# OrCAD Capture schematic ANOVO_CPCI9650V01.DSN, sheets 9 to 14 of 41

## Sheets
9 -GMCH DMI & STRAP (3 of 7): size C; title: 09--GMCH DMI & STRAP (3 of 7)
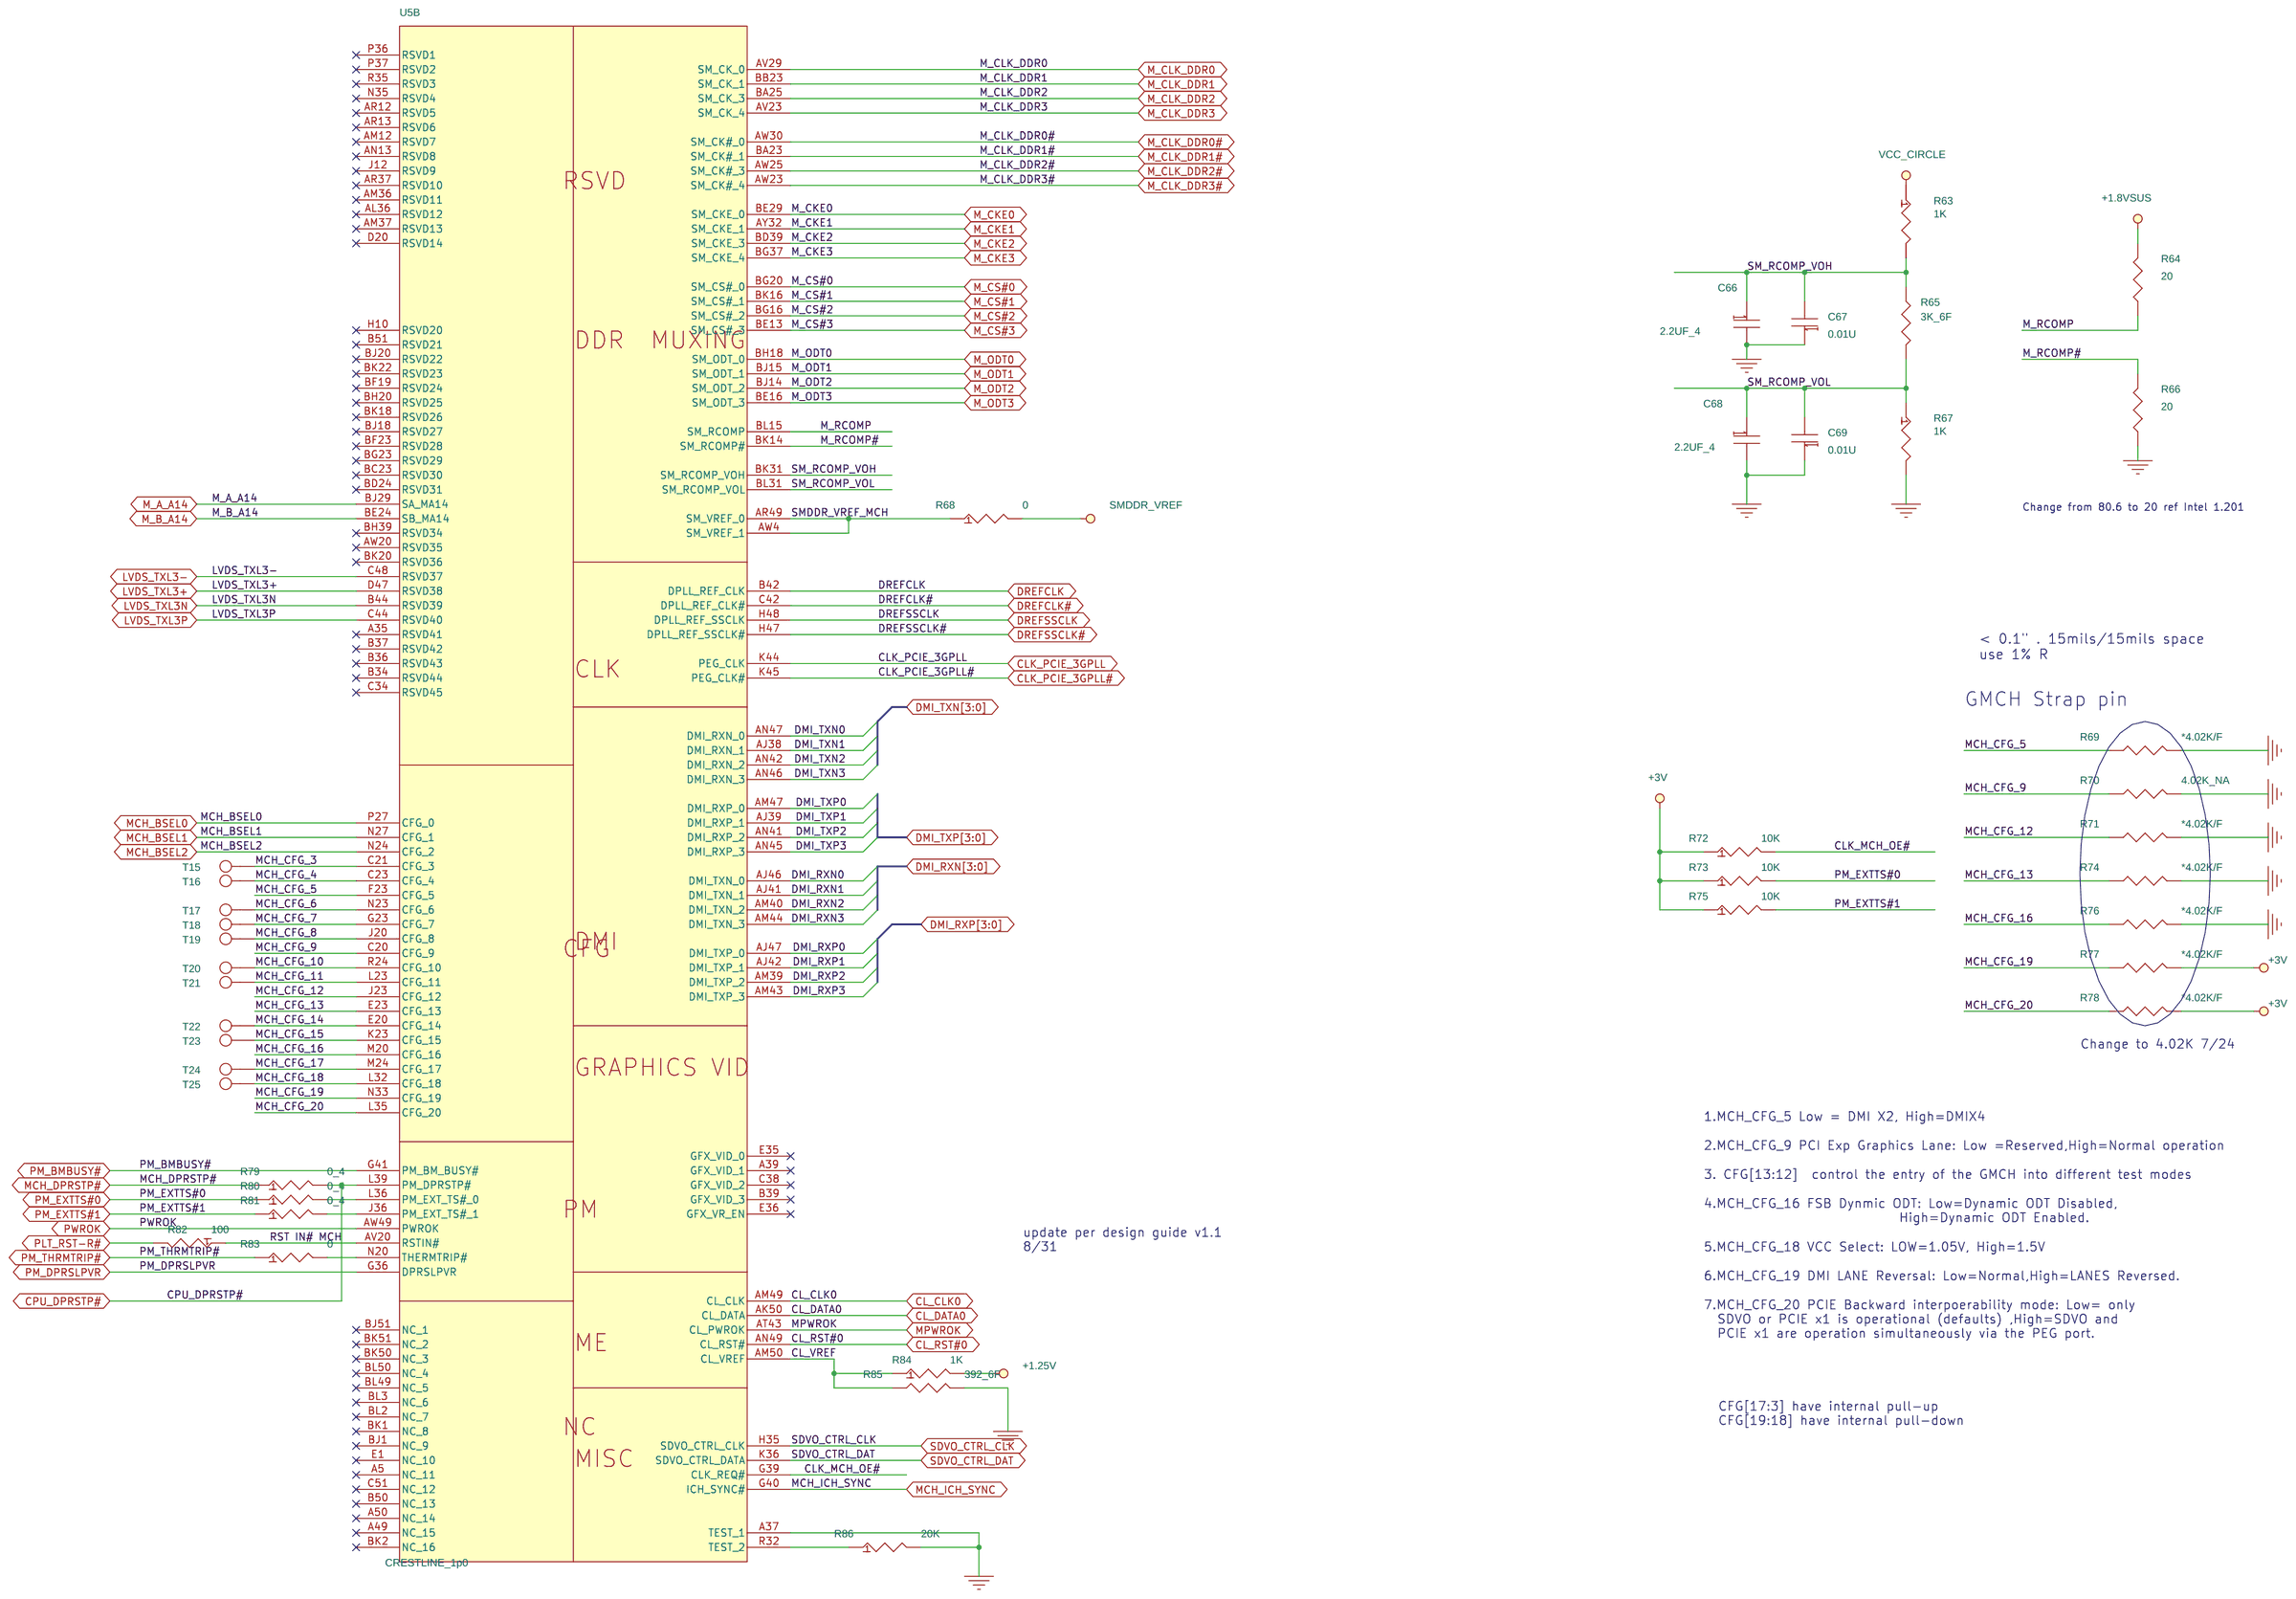
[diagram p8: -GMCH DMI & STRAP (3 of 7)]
10 -GMCH VGA (4 of 7): size A2; title: 10--GMCH VGA (4 of 7)
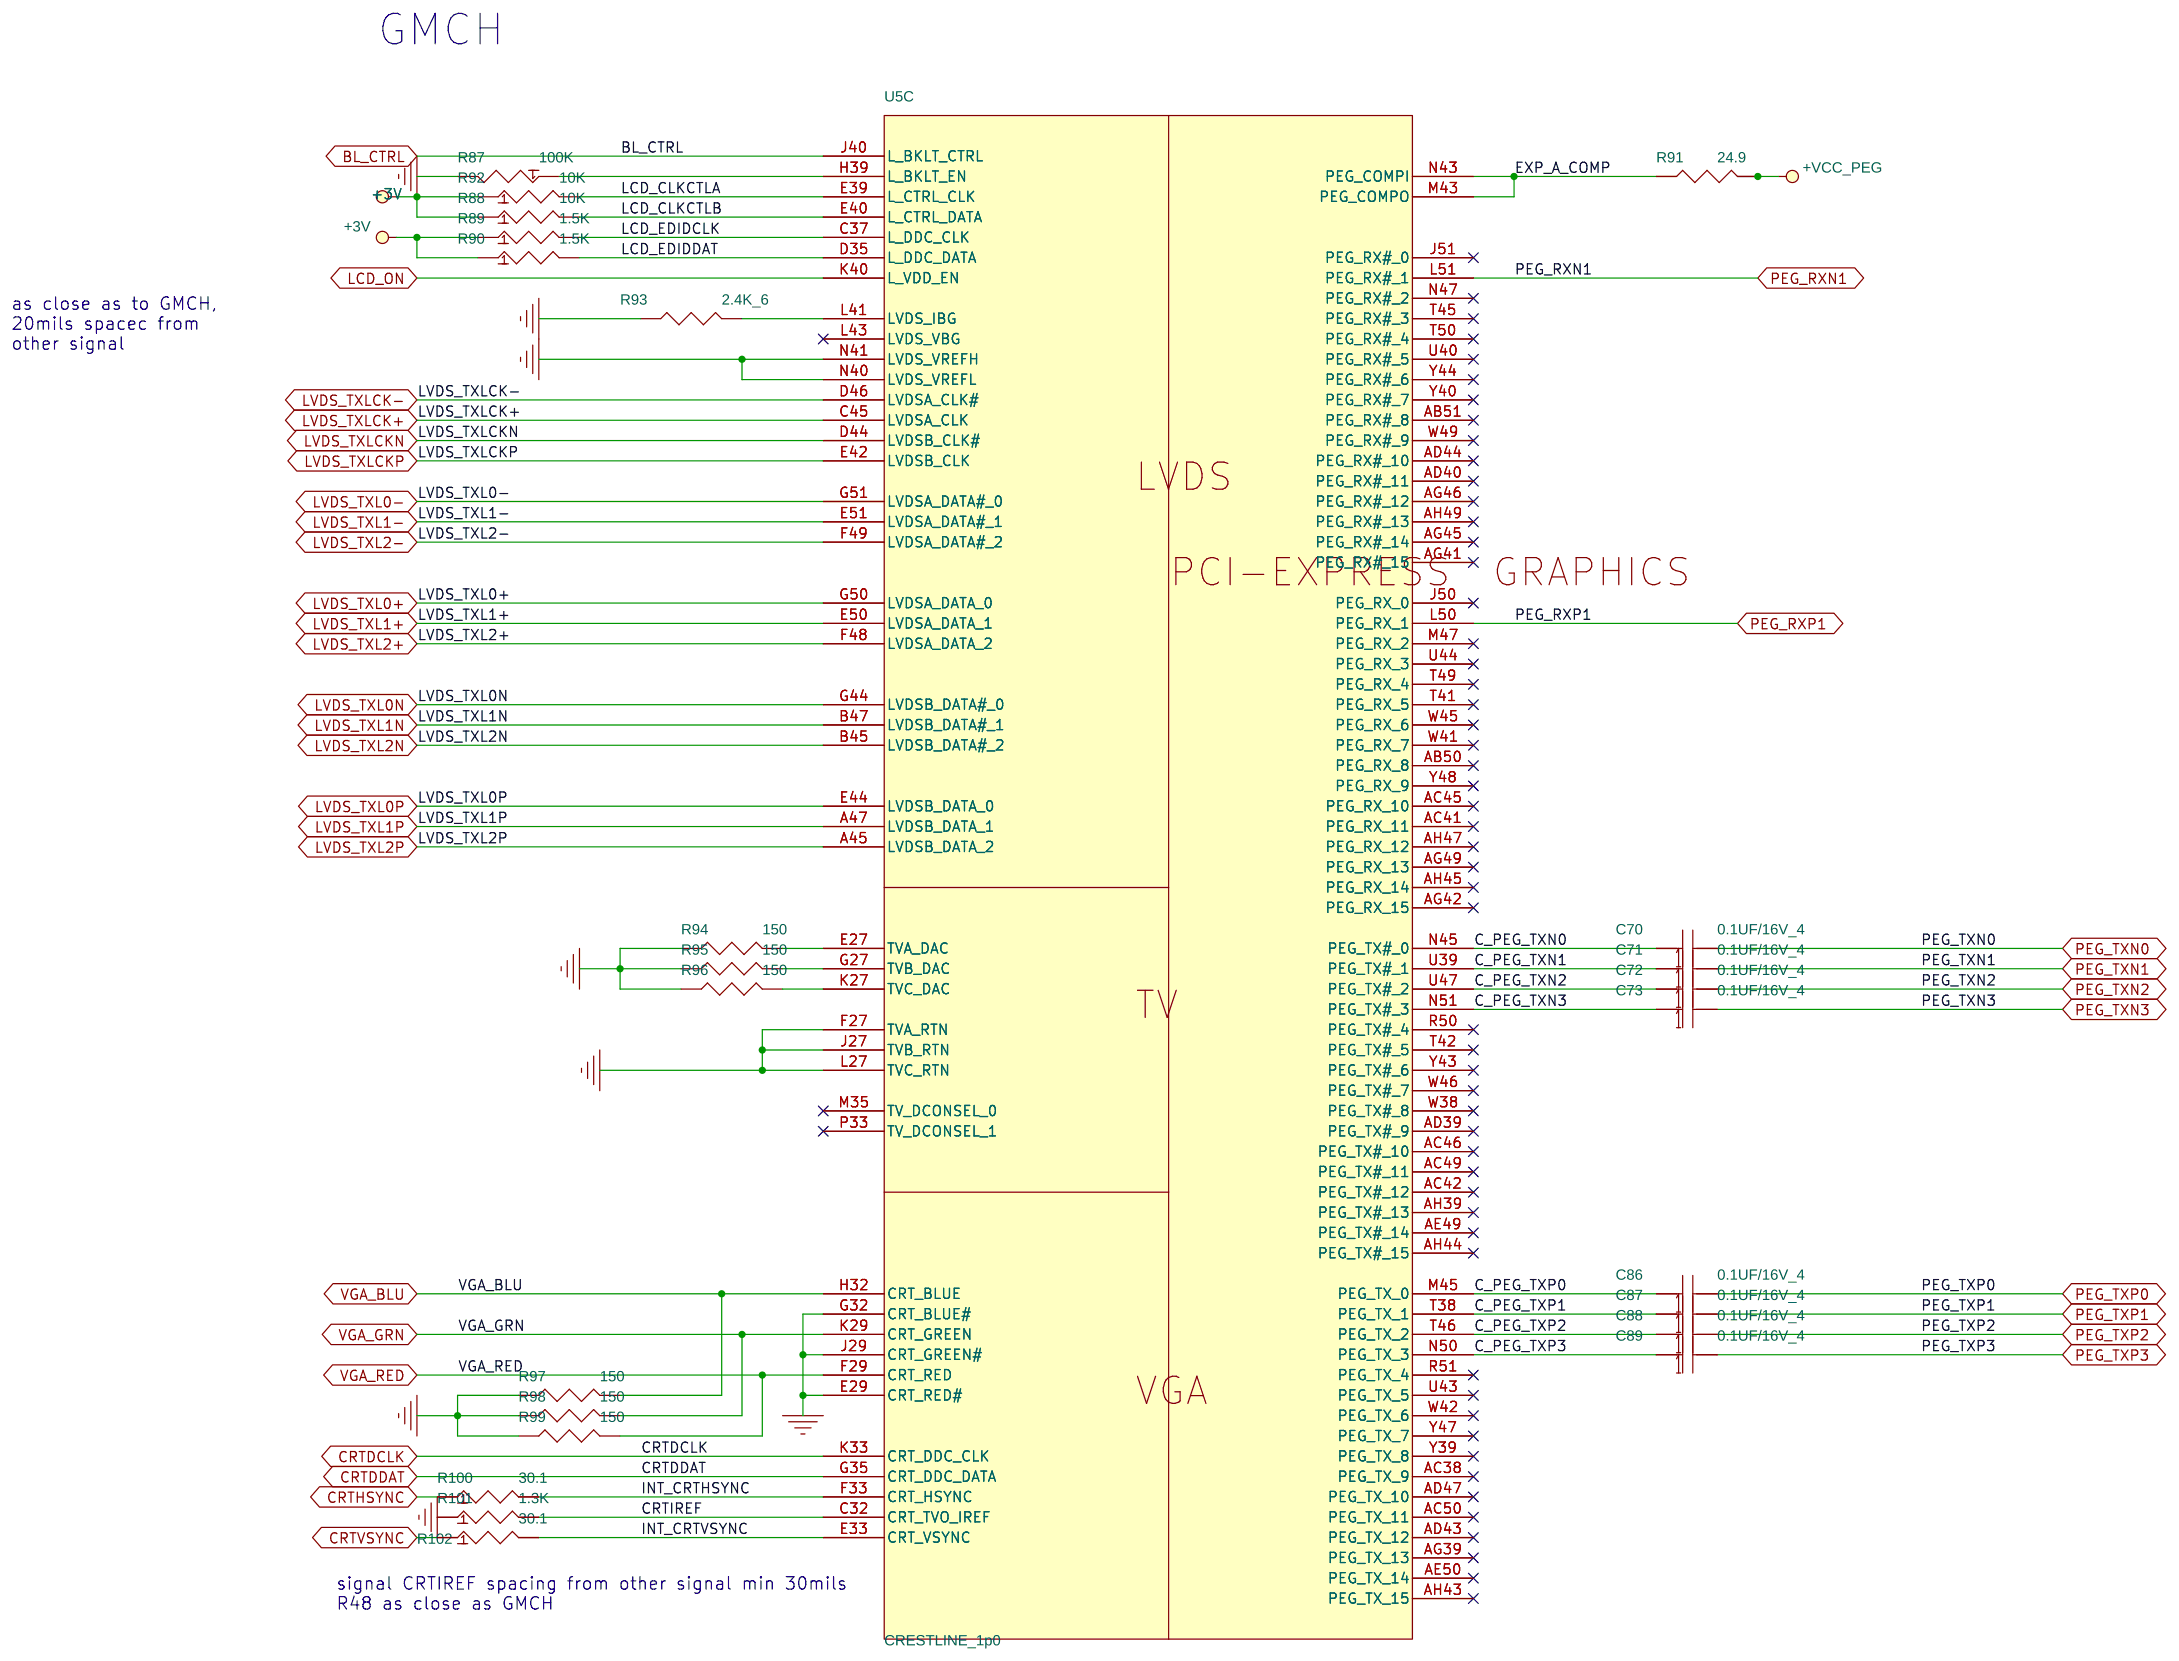
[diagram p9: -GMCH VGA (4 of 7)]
11 -GMCH POWER 1 (5 of 7): size C; title: 11--GMCH POWER 1 (5 of 7)
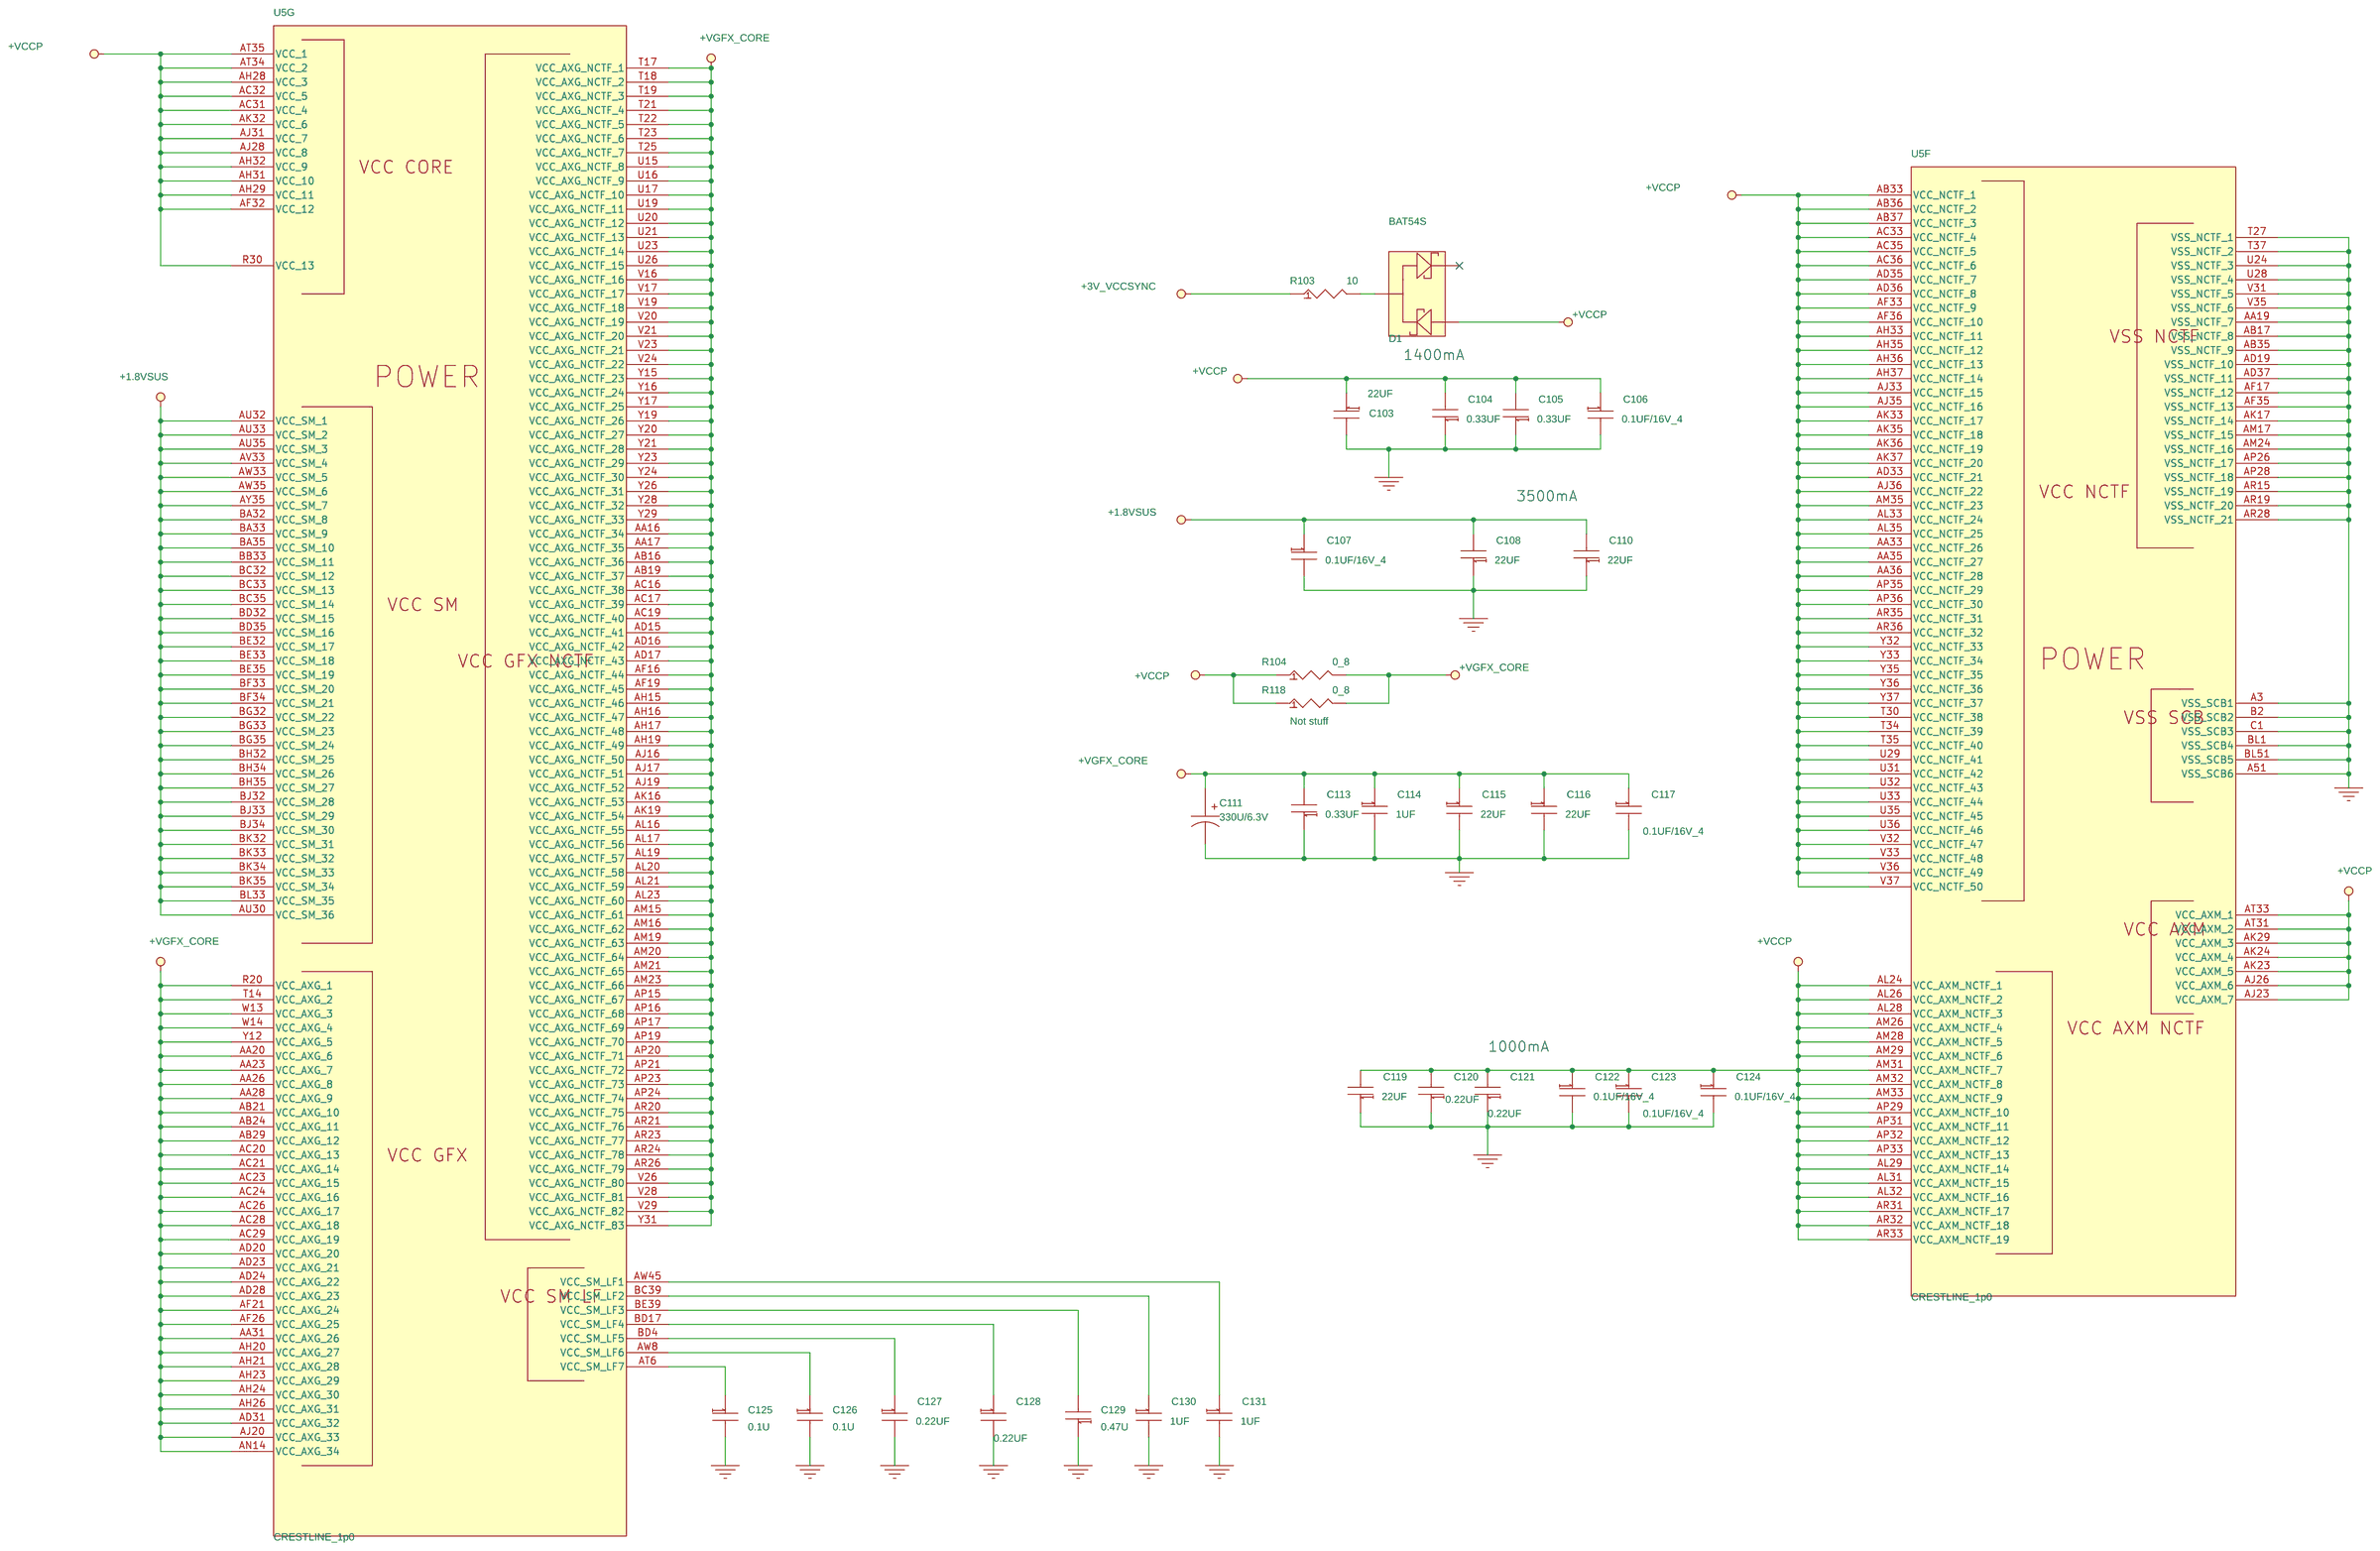
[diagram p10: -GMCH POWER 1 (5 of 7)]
12 -GMCH POWER 2 (6 of 7): size C; title: 12--GMCH POWER 2 (6 of 7)
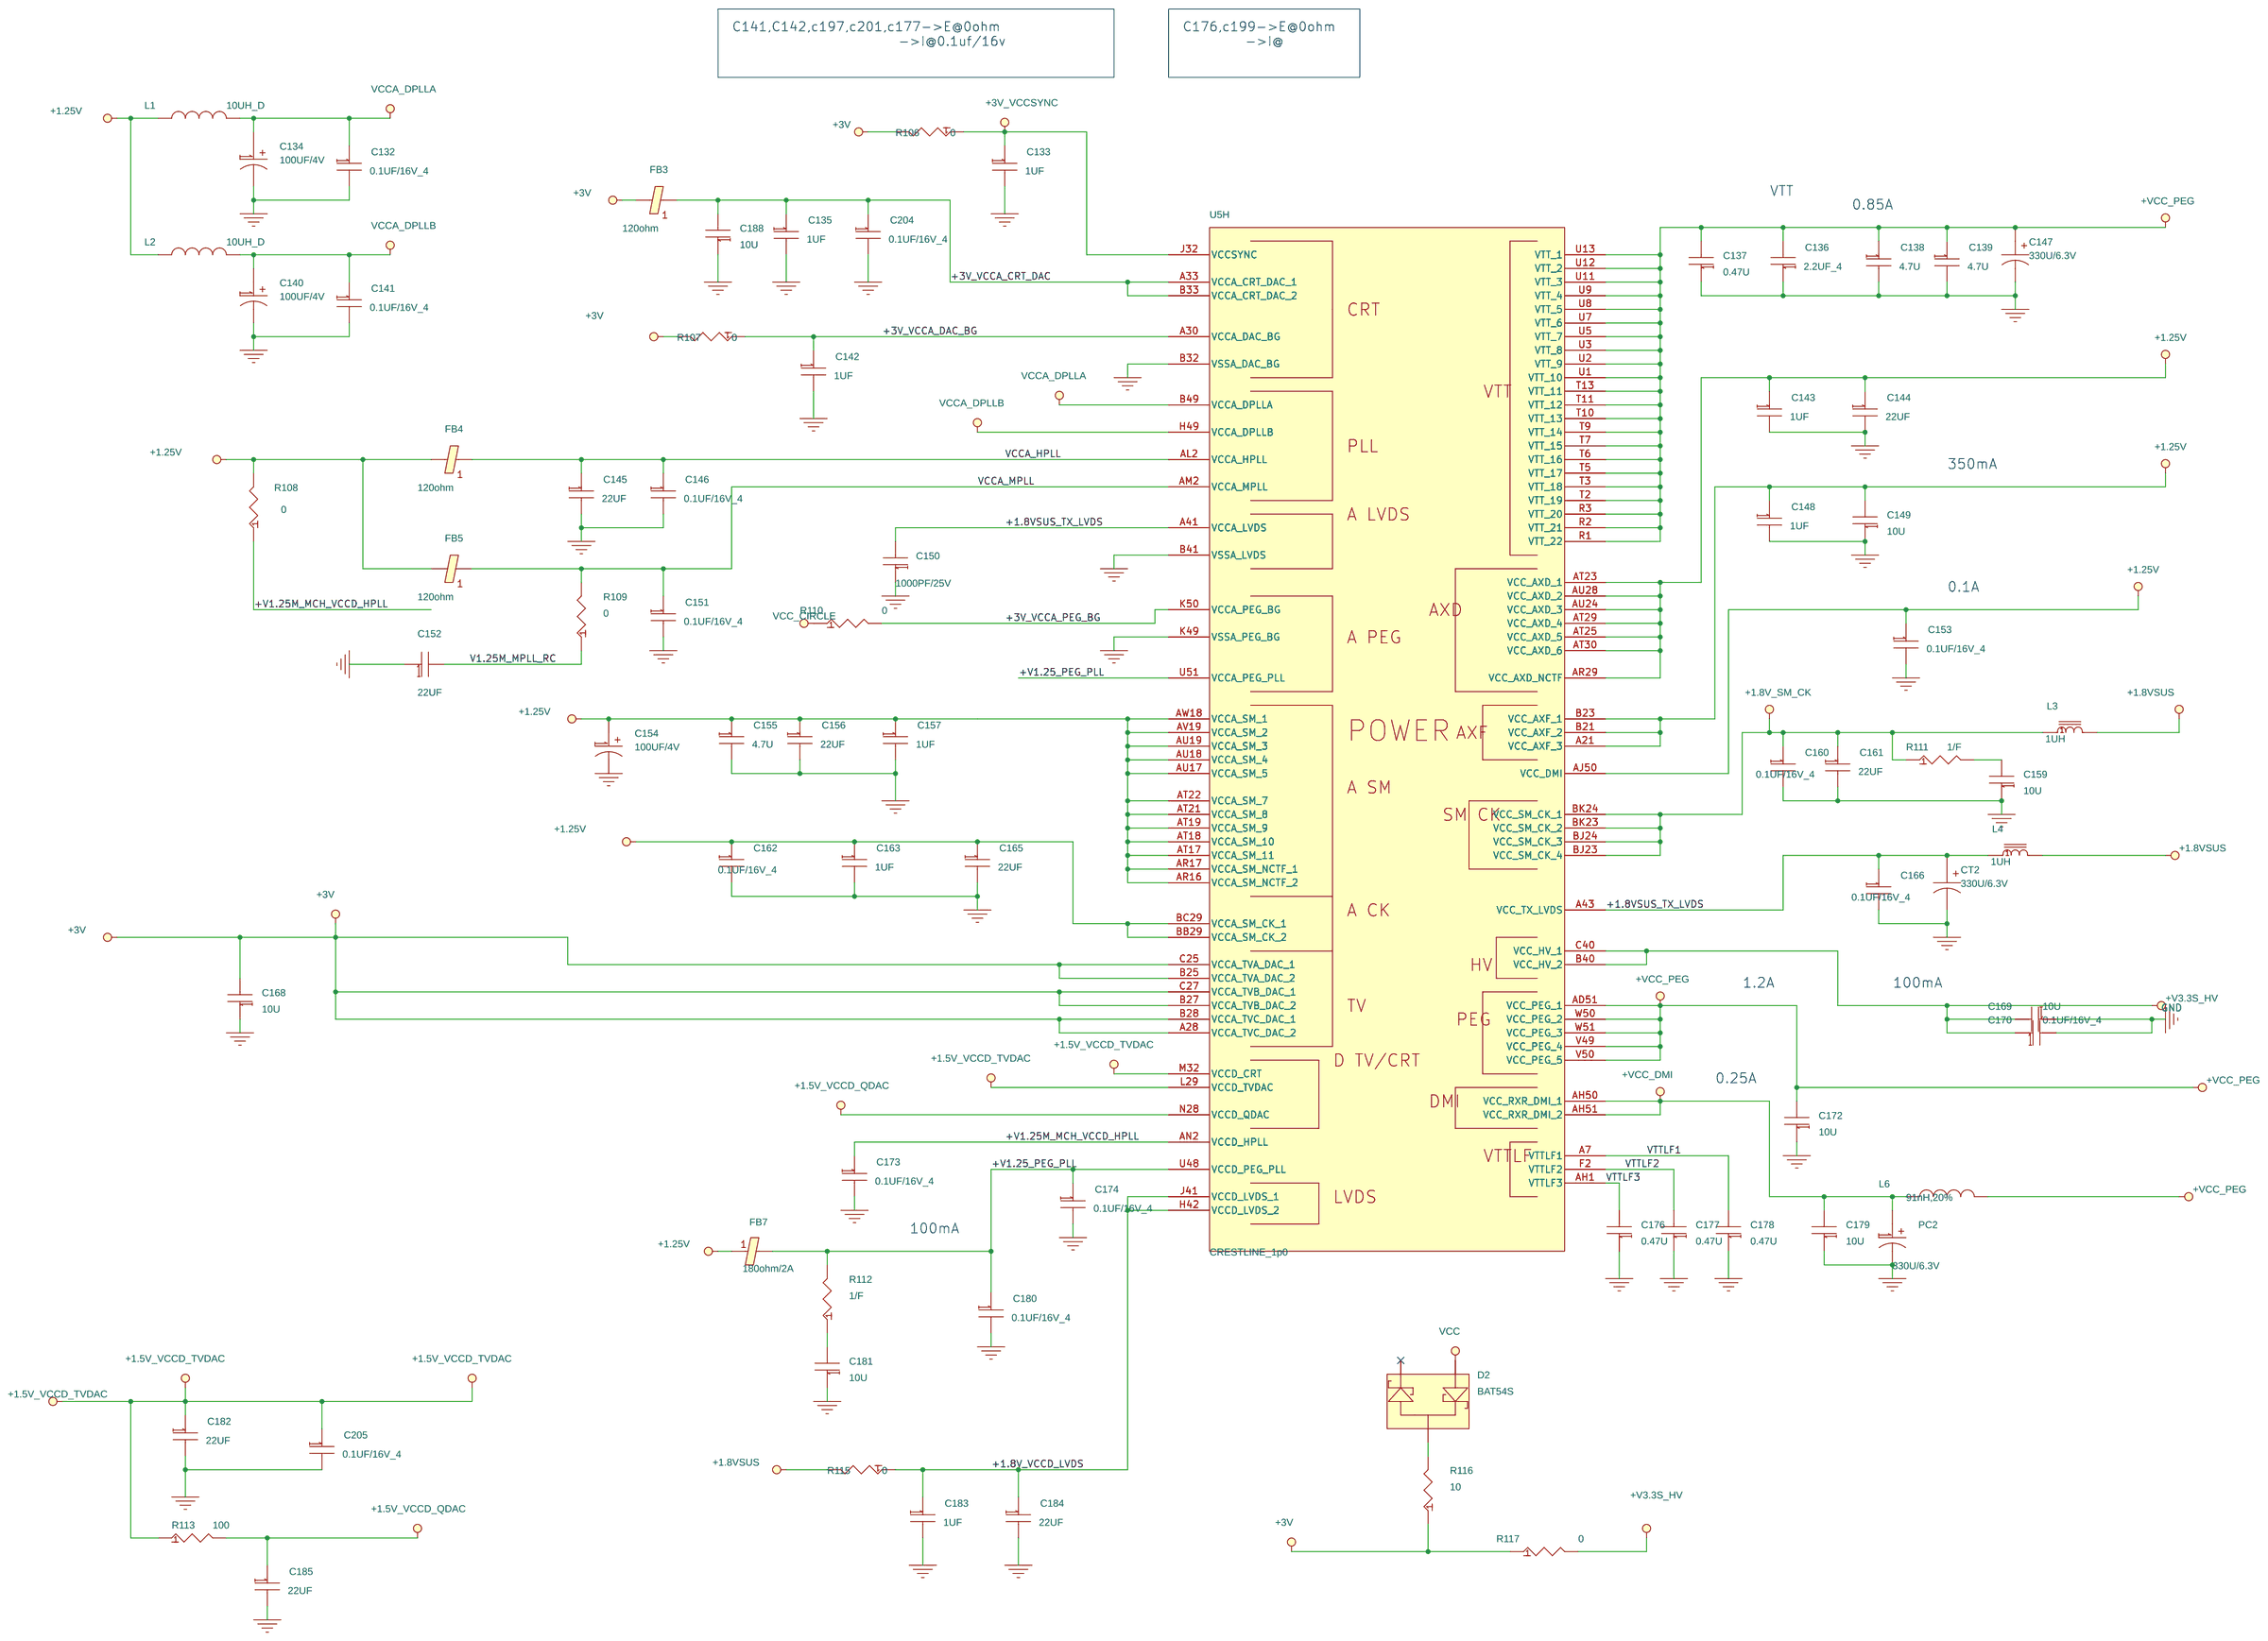
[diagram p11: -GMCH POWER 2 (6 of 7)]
13 -GMCH GND (7 of 7): size C; title: 13--GMCH GND (7 of 7)
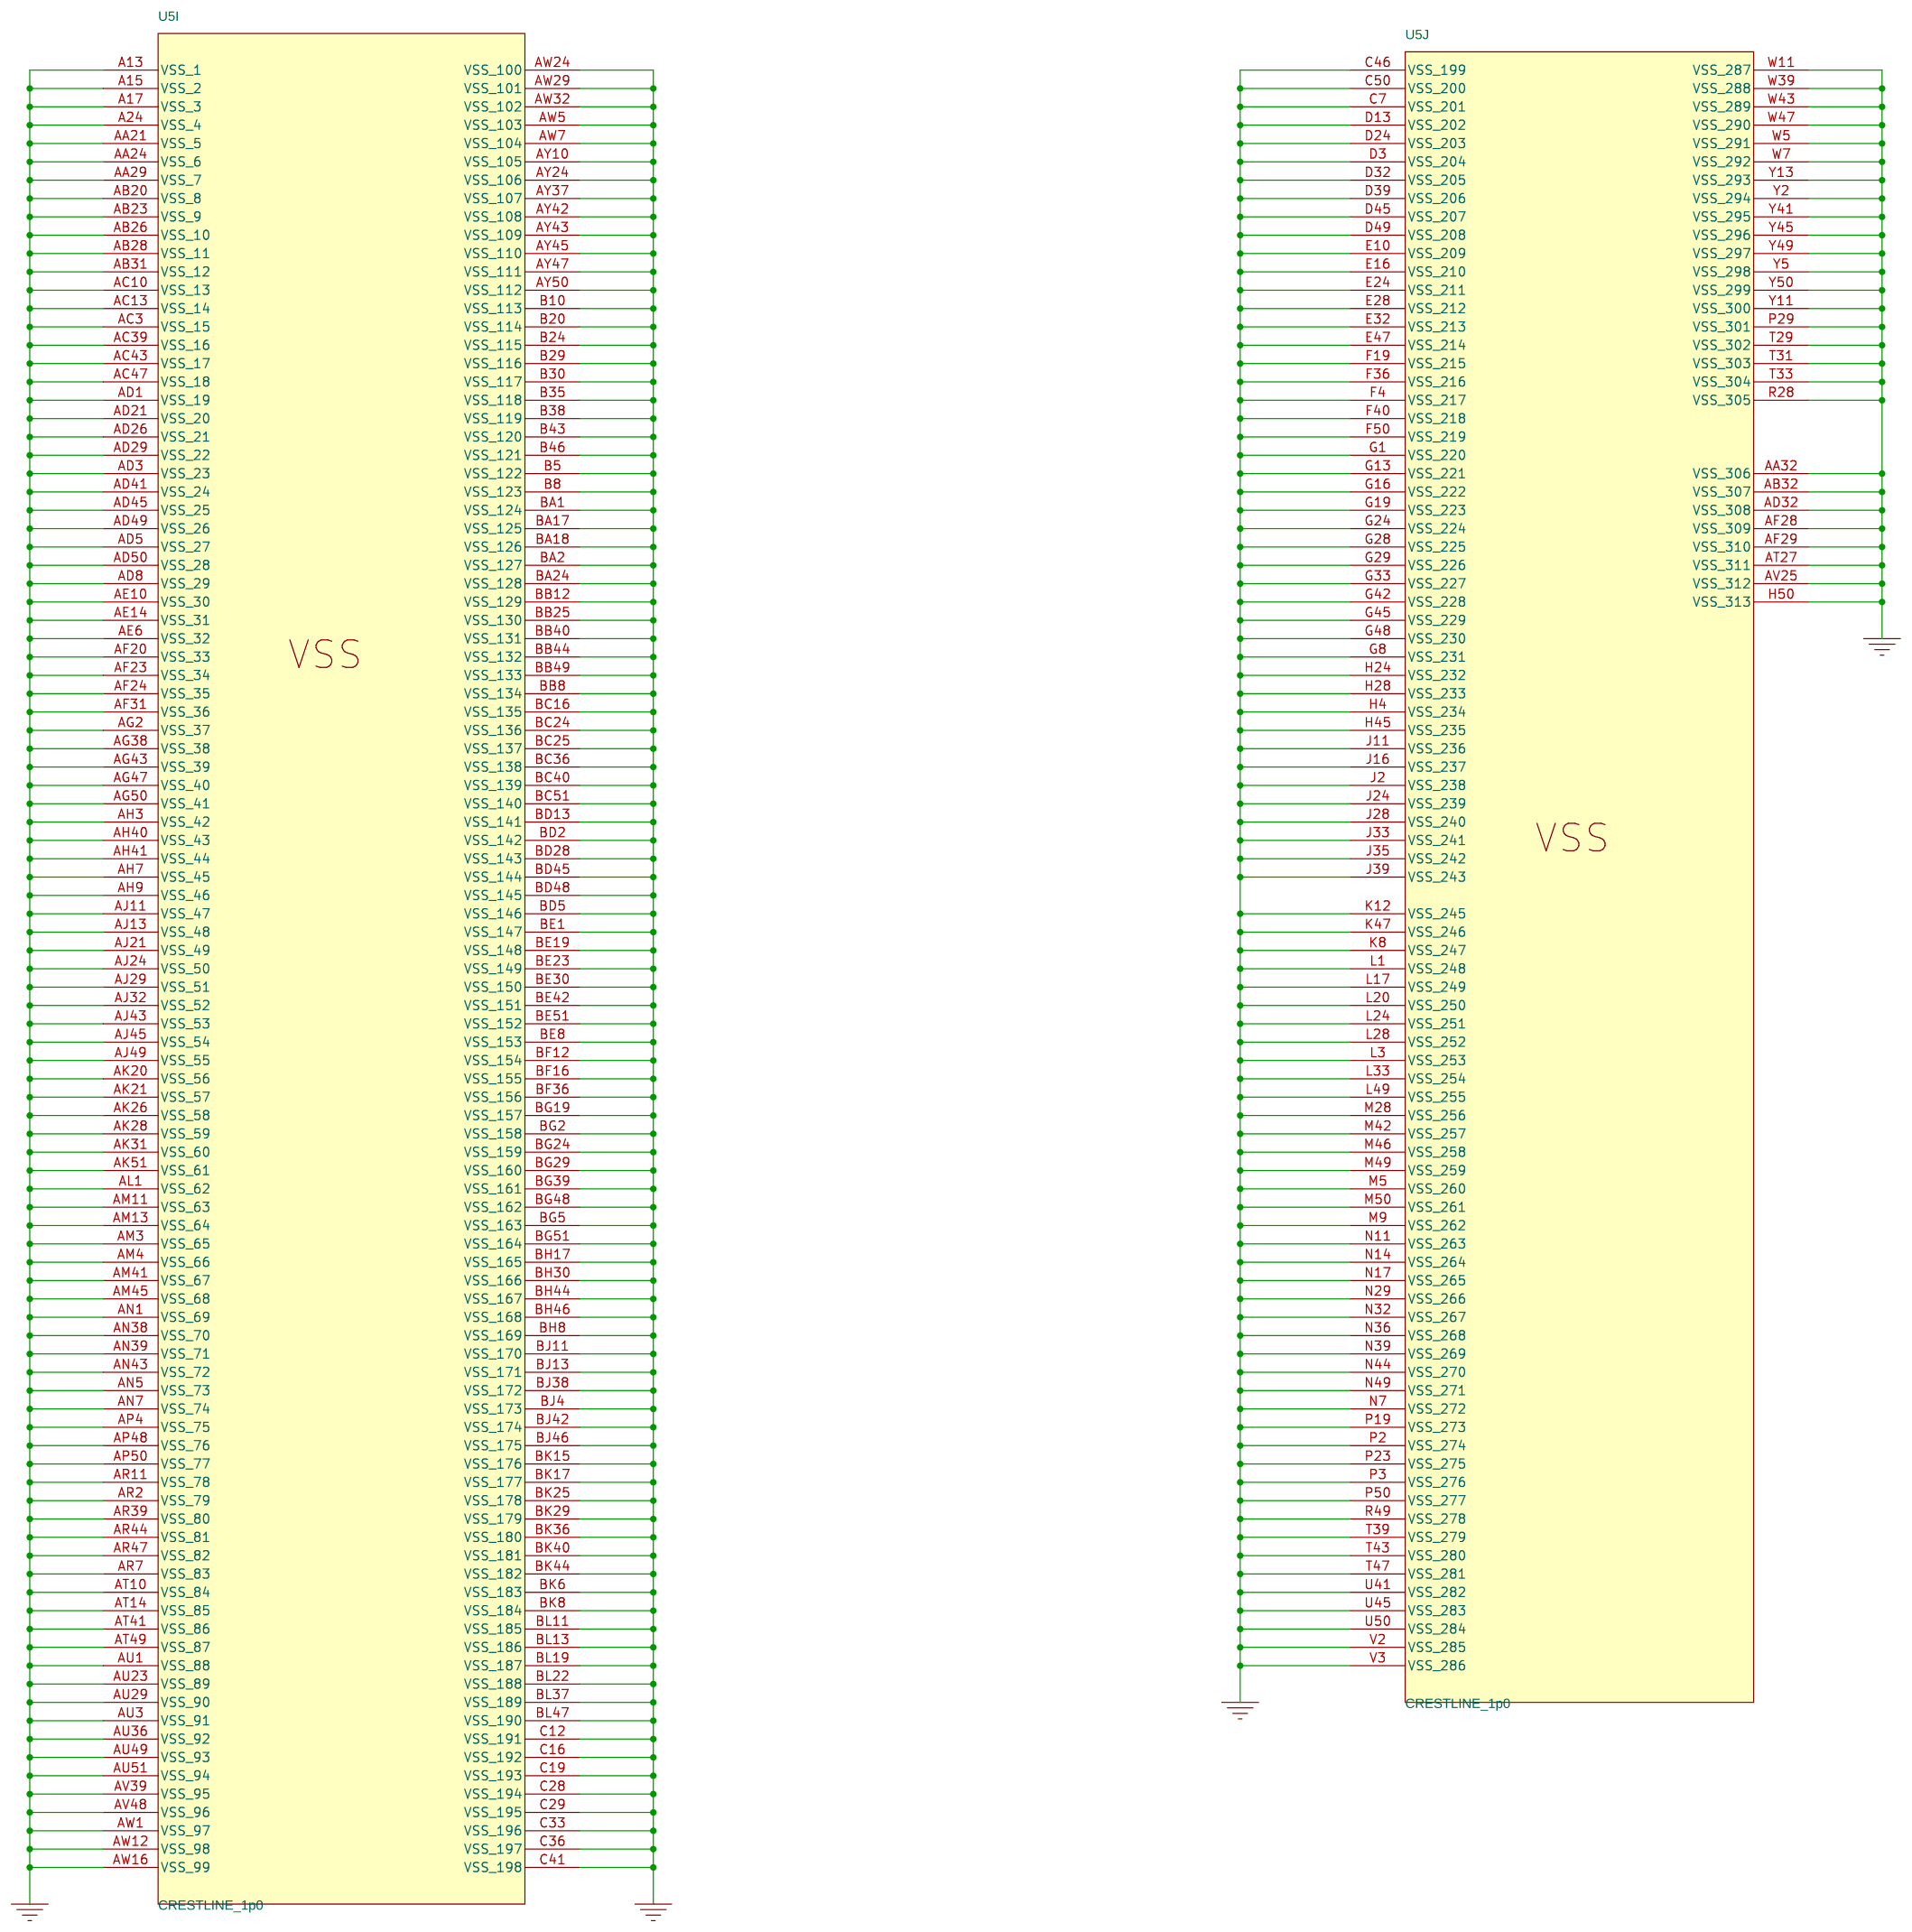
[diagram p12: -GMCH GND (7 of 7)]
14 -SO-DIMM & TERMINATOR: size C; title: 14--SO-DIMM & TERMINATOR
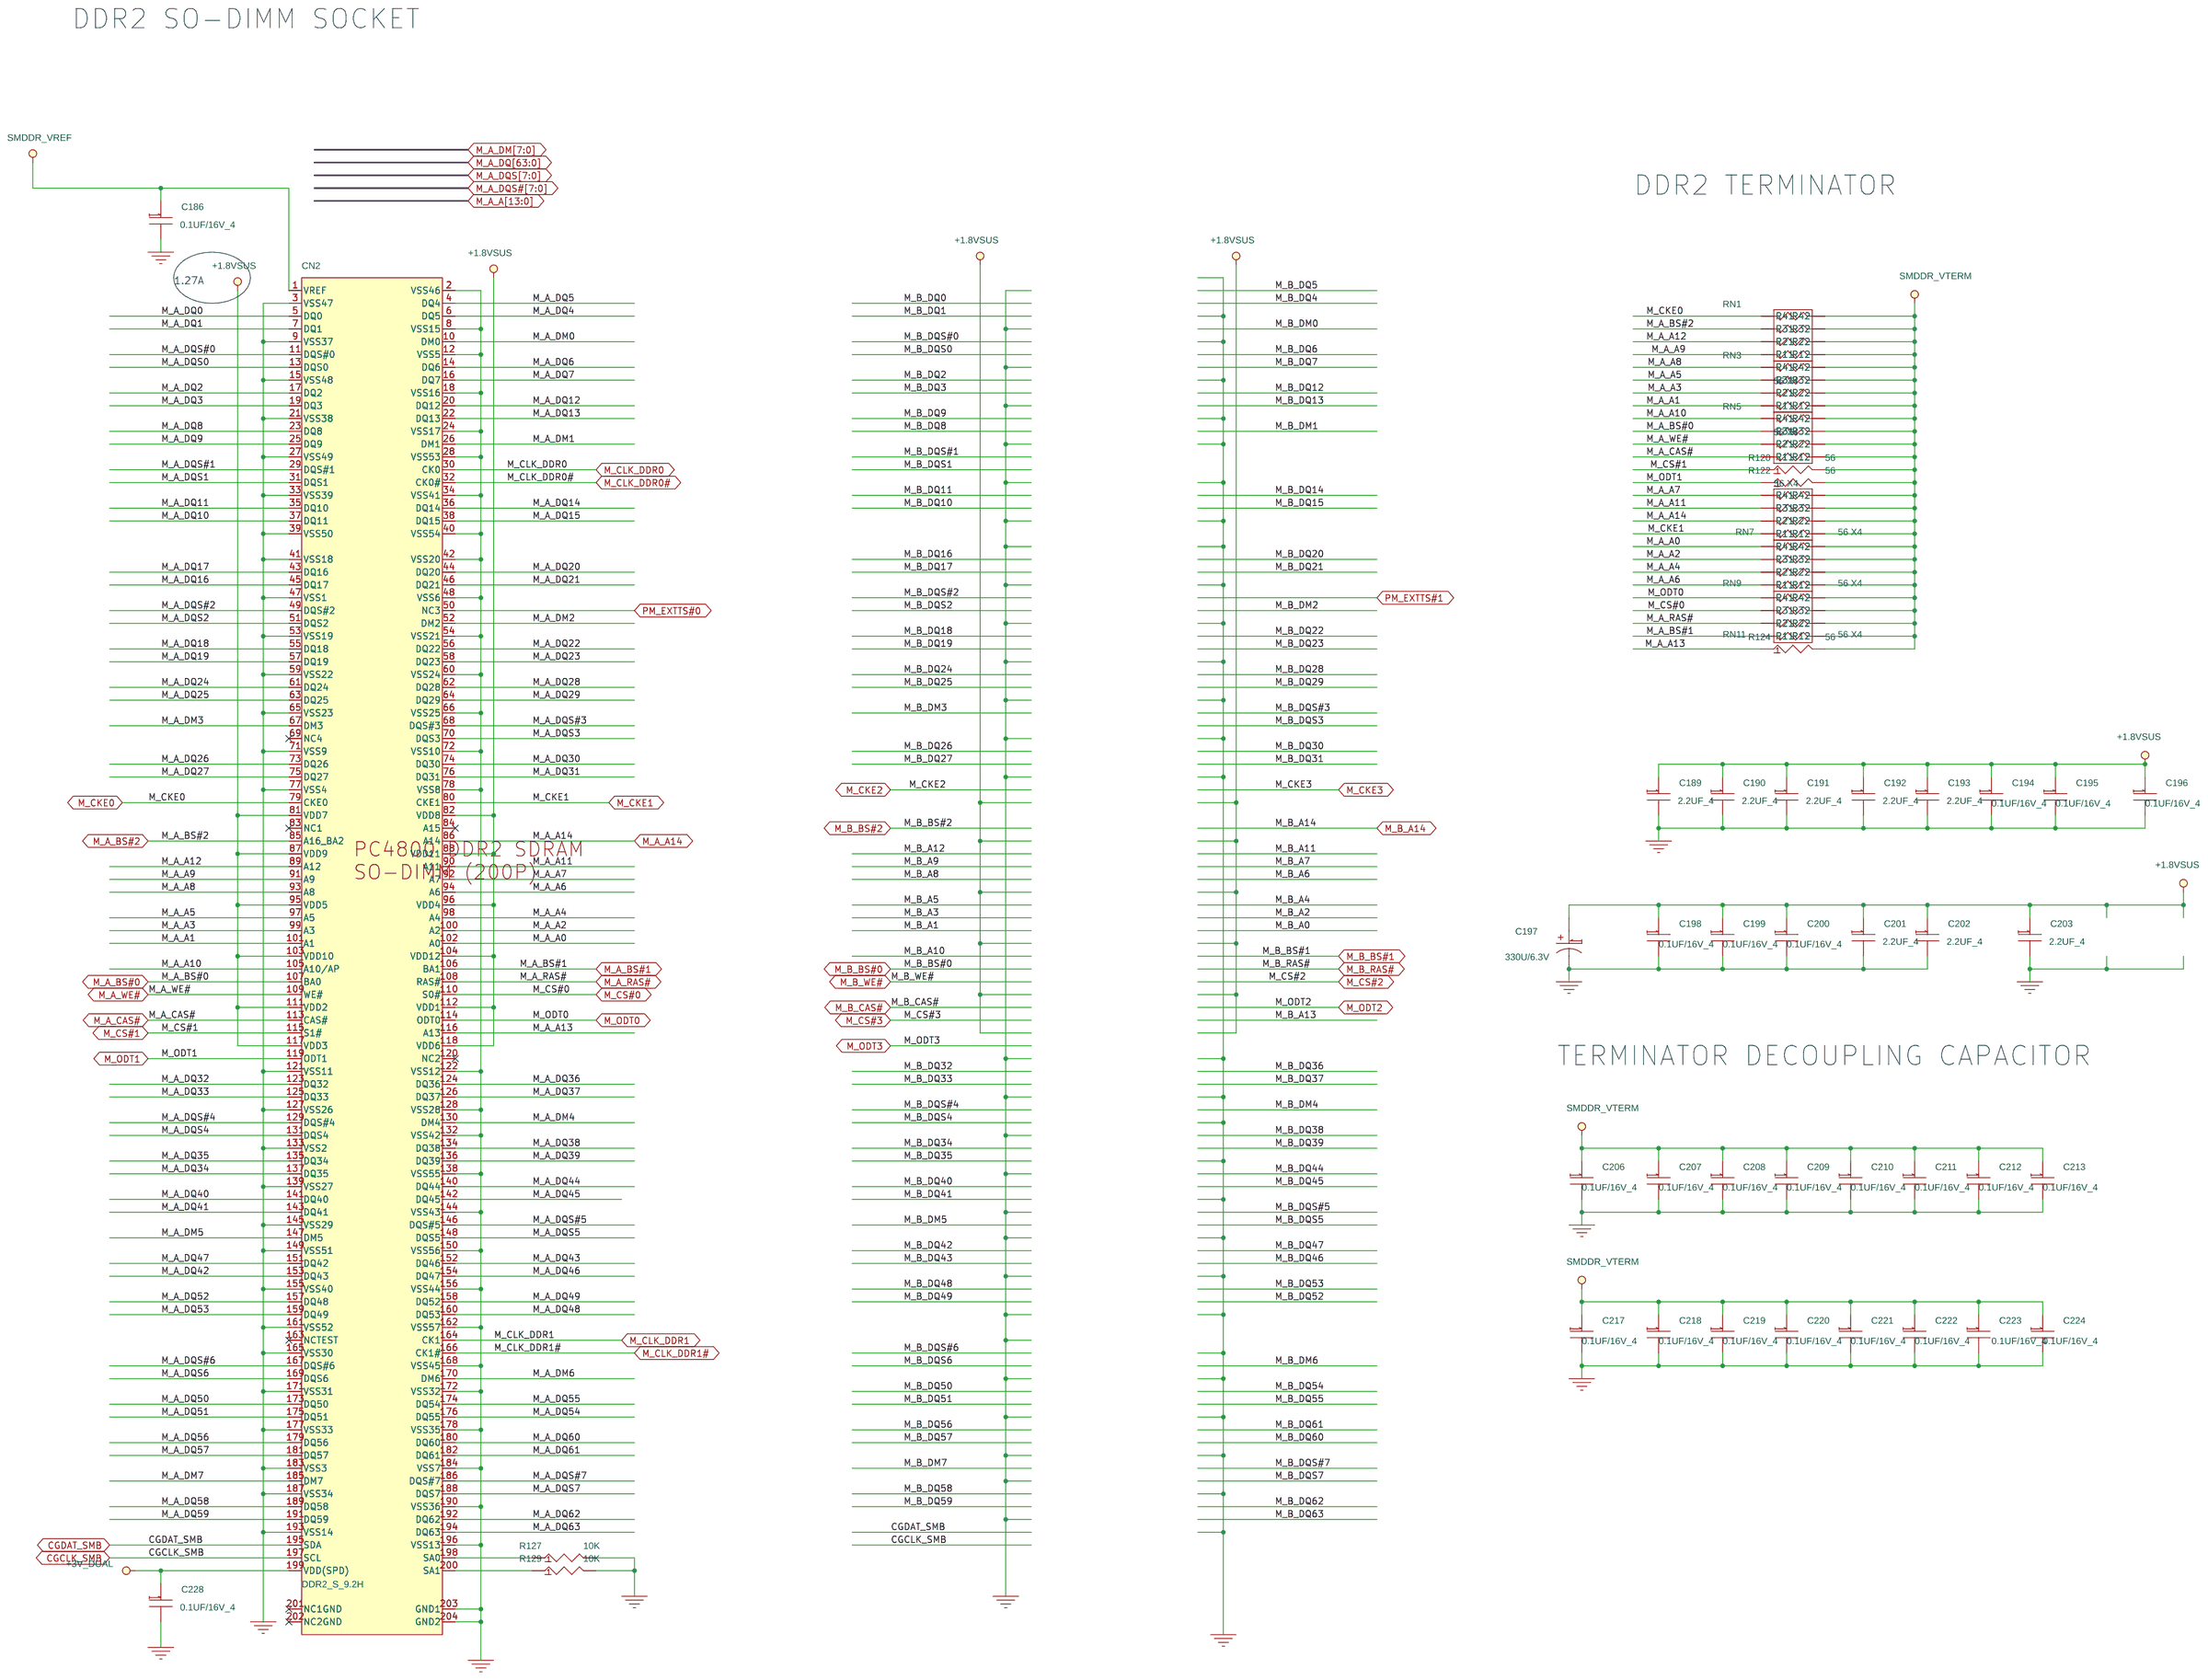
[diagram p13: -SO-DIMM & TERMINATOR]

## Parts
sheet -GMCH DMI & STRAP (3 of 7)
C66  2.2UF_4  [0402D]
C67  0.01U  [0402D]
C68  2.2UF_4  [0402D]
C69  0.01U  [0402D]
R63  1K  [0402D]
R64  20  [0402D]
R65  3K_6F  [0603D]
R66  20  [0402D]
R67  1K  [0402D]
R68  0  [0603D]
R69  *4.02K/F  [0402D]
R70  4.02K_NA  [0402D]
R71  *4.02K/F  [0402D]
R72  10K  [0402D]
R73  10K  [0402D]
R74  *4.02K/F  [0402D]
R75  10K  [0402D]
R76  *4.02K/F  [0402D]
R77  *4.02K/F  [0402D]
R78  *4.02K/F  [0402D]
R79  0_4  [0402D]
R80  0_4  [0402D]
R81  0_4  [0402D]
R82  100  [0402D]
R83  0  [0603D]
R84  1K  [0402D]
R85  392_6F  [0603D]
R86  20K  [0402D]
T15  PAD  [pad-c3050]
T16  PAD  [pad-c3050]
T17  PAD  [pad-c3050]
T18  PAD  [pad-c3050]
T19  PAD  [pad-c3050]
T20  PAD  [pad-c3050]
T21  PAD  [pad-c3050]
T22  PAD  [pad-c3050]
T23  PAD  [pad-c3050]
T24  PAD  [pad-c3050]
T25  PAD  [pad-c3050]
sheet -GMCH POWER 1 (5 of 7)
C103  22UF  [0805D]
C104  0.33UF  [0402D]
C105  0.33UF  [0402D]
C106  0.1UF/16V_4  [0402D]
C107  0.1UF/16V_4  [0402D]
C108  22UF  [0805D]
C110  22UF  [0805D]
C111  330U/6.3V  [1812A]
C113  0.33UF  [0402D]
C114  1UF  [0402D]
C115  22UF  [0805D]
C116  22UF  [0805D]
C117  0.1UF/16V_4  [0402D]
C119  22UF  [0805D]
C120  0.22UF  [0603D]
C121  0.22UF  [0603D]
C122  0.1UF/16V_4  [0402D]
C123  0.1UF/16V_4  [0402D]
C124  0.1UF/16V_4  [0402D]
C125  0.1U  [0402D]
C126  0.1U  [0402D]
C127  0.22UF  [0603D]
C128  0.22UF  [0603D]
C129  0.47U  [0603D]
C130  1UF  [0402D]
C131  1UF  [0402D]
D1  BAT54S  [SOT23N_5]
R103  10  [0603D]
R104  0_8  [0805D]
R118  0_8  [0805D]
sheet -GMCH POWER 2 (6 of 7)
C132  0.1UF/16V_4  [0402D]
C133  1UF  [0402D]
C134  100UF/4V  [C3530]
C135  1UF  [0402D]
C136  2.2UF_4  [0402D]
C137  0.47U  [0603D]
C138  4.7U  [0805D]
C139  4.7U  [0805D]
C140  100UF/4V  [C3530]
C141  0.1UF/16V_4  [0402D]
C142  1UF  [0402D]
C143  1UF  [0402D]
C144  22UF  [0805D]
C145  22UF  [0805D]
C146  0.1UF/16V_4  [0402D]
C147  330U/6.3V  [1812A]
C148  1UF  [0402D]
C149  10U  [0805D]
C150  1000PF/25V  [0402D]
C151  0.1UF/16V_4  [0402D]
C152  22UF  [0805D]
C153  0.1UF/16V_4  [0402D]
C154  100UF/4V  [C3530]
C155  4.7U  [0805D]
C156  22UF  [0805D]
C157  1UF  [0402D]
C159  10U  [0805D]
C160  0.1UF/16V_4  [0402D]
C161  22UF  [0805D]
C162  0.1UF/16V_4  [0402D]
C163  1UF  [0402D]
C165  22UF  [0805D]
C166  0.1UF/16V_4  [0402D]
C168  10U  [0805D]
C169  10U  [0805D]
C170  0.1UF/16V_4  [0402D]
C172  10U  [0805D]
C173  0.1UF/16V_4  [0402D]
C174  0.1UF/16V_4  [0402D]
C176  0.47U  [0603D]
C177  0.47U  [0603D]
C178  0.47U  [0603D]
C179  10U  [0805D]
C180  0.1UF/16V_4  [0402D]
C181  10U  [0805D]
C182  22UF  [0805D]
C183  1UF  [0402D]
C184  22UF  [0805D]
C185  22UF  [0805D]
C188  10U  [0805D]
C204  0.1UF/16V_4  [0402D]
C205  0.1UF/16V_4  [0402D]
CT2  330U/6.3V  [1812A]
D2  BAT54S  [SOT23N_5]
FB3  120ohm  [0603D]
FB4  120ohm  [0603D]
FB5  120ohm  [0603D]
FB7  180ohm/2A  [0805D]
L1  10UH_D  [0805D]
L2  10UH_D  [0805D]
L3  1UH  [0805D]
L4  1UH  [0805D]
L6  91nH,20%  [L32X25-22]
PC2  330U/6.3V  [1812A]
R106  0  [0603D]
R107  0  [0603D]
R108  0  [0603D]
R109  0  [0603D]
R110  0  [0603D]
R111  1/F  [0402D]
R112  1/F  [0402D]
R113  100  [0402D]
R115  0  [0603D]
R116  10  [0603D]
R117  0  [0603D]
U5  CRESTLINE_1p0  [fbga1299-intel-crestline]  (sections A,B,C,D,E,F,G,H,I,J)
sheet -GMCH VGA (4 of 7)
C70  0.1UF/16V_4  [0402D]
C71  0.1UF/16V_4  [0402D]
C72  0.1UF/16V_4  [0402D]
C73  0.1UF/16V_4  [0402D]
C86  0.1UF/16V_4  [0402D]
C87  0.1UF/16V_4  [0402D]
C88  0.1UF/16V_4  [0402D]
C89  0.1UF/16V_4  [0402D]
R87  100K  [0402D]
R88  10K  [0402D]
R89  1.5K  [0402D]
R90  1.5K  [0402D]
R91  24.9  [0402D]
R92  10K  [0402D]
R93  2.4K_6  [0603D]
R94  150  [0402D]
R95  150  [0402D]
R96  150  [0402D]
R97  150  [0402D]
R98  150  [0402D]
R99  150  [0402D]
R100  30.1  [0603D]
R101  1.3K  [0603D]
R102  30.1  [0603D]
sheet -SO-DIMM & TERMINATOR
C186  0.1UF/16V_4  [0402D]
C189  2.2UF_4  [0402D]
C190  2.2UF_4  [0402D]
C191  2.2UF_4  [0402D]
C192  2.2UF_4  [0402D]
C193  2.2UF_4  [0402D]
C194  0.1UF/16V_4  [0402D]
C195  0.1UF/16V_4  [0402D]
C196  0.1UF/16V_4  [0402D]
C197  330U/6.3V  [1812A]
C198  0.1UF/16V_4  [0402D]
C199  0.1UF/16V_4  [0402D]
C200  0.1UF/16V_4  [0402D]
C201  2.2UF_4  [0402D]
C202  2.2UF_4  [0402D]
C203  2.2UF_4  [0402D]
C206  0.1UF/16V_4  [0402D]
C207  0.1UF/16V_4  [0402D]
C208  0.1UF/16V_4  [0402D]
C209  0.1UF/16V_4  [0402D]
C210  0.1UF/16V_4  [0402D]
C211  0.1UF/16V_4  [0402D]
C212  0.1UF/16V_4  [0402D]
C213  0.1UF/16V_4  [0402D]
C217  0.1UF/16V_4  [0402D]
C218  0.1UF/16V_4  [0402D]
C219  0.1UF/16V_4  [0402D]
C220  0.1UF/16V_4  [0402D]
C221  0.1UF/16V_4  [0402D]
C222  0.1UF/16V_4  [0402D]
C223  0.1UF/16V_4  [0402D]
C224  0.1UF/16V_4  [0402D]
C228  0.1UF/16V_4  [0402D]
CN2  DDR2_S_9.2H  [SODIMM_DDR2]
R120  56  [0402D]
R122  56  [0402D]
R124  56  [0402D]
R127  10K  [0402D]
R129  10K  [0402D]
RN1  56 X4  [RP_8P4R_0804B]
RN3  56 X4  [RP_8P4R_0804B]
RN5  56 X4  [RP_8P4R_0804B]
RN7  56 X4  [RP_8P4R_0804B]
RN9  56 X4  [RP_8P4R_0804B]
RN11  56 X4  [RP_8P4R_0804B]

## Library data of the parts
C66 C68 C136 C189-C193 C201-C203 = CAP_NP: ANOVO DESCRIPTION: CAP;2.2U ,6.3V ,10% ,0402 ,X7R ,SMT; ANOVO PART NUMBER: 272041225201
C67 C69 = CAP_NP: ANOVO DESCRIPTION: CAP;0.01U ,16V ,10% ,0402 ,X7R ,SMT; ANOVO PART NUMBER: 272043103201; Part Type: CCAP
R63 R67 R84 = R_v2: ANOVO DESCRIPTION: RES;1K ,1/16W ,1% ,0402 ,SMT; ANOVO PART NUMBER: 271040102101; Part Type: RESISTOR
R64 R66 = R_0: ANOVO DESCRIPTION: RES;20 ,1/16W ,1% ,0402 ,SMT; ANOVO PART NUMBER: 271040200101; BACKSIDE: 0; Part Type: RESISTOR; SMT: YES
R65 = R_0: ANOVO DESCRIPTION: RES;3K ,1/10W ,1% ,0603 ,SMT; ANOVO PART NUMBER: 271071302101; BACKSIDE: 0; Part Number: CS23012FB16; Part Type: RESISTOR; SMT: YES; Tolerance: 1%
R68 R83 R106-R110 R115 R117 = R_v2: ANOVO DESCRIPTION: RES;0 ,1/10W ,5% ,0603 ,SMT; ANOVO PART NUMBER: 271071000301; Part Type: RESISTOR
R69-R71 R74 R76-R78 = R_2: 2ND PART FIELD: CS24022FB05; Function Code: CLG; NOTE: NO STORE; Part Number: CS24022FB05
R72 R73 R75 R88 R92 R127 R129 = R_v2: ANOVO DESCRIPTION: RES;10K ,1/16W ,5% ,0402 ,SMT; ANOVO PART NUMBER: 271040103301; BACKSIDE: 0; Part Type: RESISTOR; SMT: YES
R79-R81 = R_v2: ANOVO DESCRIPTION: RES;0 ,1/16W ,5% ,0402 ,SMT; ANOVO PART NUMBER: 271040000301; BACKCOMP: YES; BACKSIDE: YES; ID: 0; Part Type: RESISTOR; SMT: YES
R82 R113 = R_v2: ANOVO DESCRIPTION: RES;100 ,1/16W ,1% ,0402 ,SMT; ANOVO PART NUMBER: 271040101101; Part Type: RESISTOR
R85 = R_0: ANOVO DESCRIPTION: RES;392 , 1/10W , 1% , 0603 ,SMT; ANOVO PART NUMBER: 271071392011; BACKSIDE: 0; Part Type: RESISTOR; SMT: YES; Tolerance: 1%
R86 = R_v2: ANOVO DESCRIPTION: RES;20K ,1/16W ,1% ,0402 ,SMT; ANOVO PART NUMBER: 271040203101; Part Type: RESISTOR; SMT: YES
T15-T25 = PAD_1: 8ND PART FIELD: BOT; Function Code: CLG; Part Number: *
C103 C108 C110 C115 C116 C119 C144 C145 C152 C156 C161 C165 C182 C184 C185 = CAP_NP: ANOVO DESCRIPTION: CAP,22U ,CR,16V ,+80-20%,0805,Y5V,SMT,TAIYO; ANOVO PART NUMBER: 272003226401; BACKSIDE: 0; Part Type: CCAP; SMT: YES
C104 C105 C113 = CAP_NP: ANOVO DESCRIPTION: CAP;0.33U ,10V ,10% ,0402 ,X5R ,SMT; ANOVO PART NUMBER: 272042334201; BACKSIDE: 0; Part Type: CCAP; SMT: YES
C70-C73 C86-C89 C106 C107 C117 C122-C124 C132 C141 C146 C151 C153 C160 C162 C166 C170 C173 C174 C180 C186 C194-C196 C198-C200 C204-C213 C217-C224 C228 = CAP_NP: ANOVO DESCRIPTION: CAP;0.1U ,16V ,+80-20% ,0402 ,Y5V ,SMT; ANOVO PART NUMBER: 272043104401; BACKSIDE: 0; Part Type: CCAP; SMT: YES
C111 C147 CT2 = CAPACITOR_POL: ANOVO DESCRIPTION: TANCAP,330U,6.3V,20%,D size, SMT; ANOVO PART NUMBER: 272633371011
C114 C130 C131 C133 C135 C142 C143 C148 C157 C163 C183 = CAP_NP: ANOVO DESCRIPTION: CAP, 1UF, 6.3V ,10%, 0402, X7R ,SMT; ANOVO PART NUMBER: 272041105200; Part Type: CCAP
C120 C121 C127 C128 = CAP_NP: ANOVO DESCRIPTION: CAP;0.22U ,16V ,10% ,0603 ,X7R ,SMT; ANOVO PART NUMBER: 272073224201; BACKSIDE: 0; Part Type: CCAP; SMT: YES
C125 C126 = CAP_NP: ANOVO DESCRIPTION: CAP;0.1U ,16V ,10% ,0402 ,X7R ,SMT; ANOVO PART NUMBER: 272043104201; Part Type: CCAP
C129 C137 C176-C178 = CAP_NP: ANOVO DESCRIPTION: CAP;0.47U ,16V ,20% ,0603 ,X5R ,SMT; ANOVO PART NUMBER: 272073474301; BACKSIDE: 0; Part Type: CCAP; SMT: YES
D1 D2 = BAT54S: ANOVO DESCRIPTION: DIODE;BAT54S,SCHOTTKY DIODE,SOT23; ANOVO PART NUMBER: 288100054021; BACKSIDE: 0; Part Type: SCHOTTKY; SMT: YES; Datasheet: \\Rdserver\norcocis\datasheet\DIODE\fairchild\BAT54.pdf
R103 R116 = R_v2: ANOVO DESCRIPTION: RES;10 ,1/10W ,1% ,0603 ,SMT; ANOVO PART NUMBER: 271071100101; BACKSIDE: 0; Part Type: RESISTOR; SMT: YES
R104 = R_v2: ANOVO DESCRIPTION: RES,0 ,1/8W ,5% ,0805 ,SMT; ANOVO PART NUMBER: 271002000301
R118 = R_v2: ANOVO DESCRIPTION: RES,0 ,1/8W ,5% ,0805 ,SMT; ANOVO PART NUMBER: 271002000301; DUMMY: Not stuff
C134 C140 C154 = CAP_T: ANOVO DESCRIPTION: TANCAP;100U ,4V,+-20%,C3530,SMT; ANOVO PART NUMBER: 272631070011; Part Type: TAN CAP
C138 C139 C155 = CAP_NP: ANOVO DESCRIPTION: CAP;4.7U ,10V ,+80-20% ,0805 ,Y5V ,SMT; ANOVO PART NUMBER: 272002475401; Part Type: CCAP
C149 C159 C168 C169 C172 C179 C181 C188 = CAP_NP: ANOVO DESCRIPTION: CAP;10U,10V,+80-20%,0805,Y5V,SMT; ANOVO PART NUMBER: 272002106401; Part Type: CCAP
C150 = CAP_NP: ANOVO DESCRIPTION: CAP;1000P ,16V ,10% ,0402 ,X7R ,SMT; ANOVO PART NUMBER: 272043102201; BACKSIDE: 0; Part Type: CCAP
FB3-FB5 = FERRITE_BEAD: ANOVO DESCRIPTION: FERRITE CHIP;120 OHM/100MHZ,0603,600MA,SMT; ANOVO PART NUMBER: 273001213200; BACKSIDE: 0; Part Type: FERRITE BEAD; SMT: YES
FB7 = FERRITE_BEAD: ANOVO DESCRIPTION: FERRITE CHIP;180 OHM/100MHZ,2A,0805,SMT; ANOVO PART NUMBER: 273001814300; BACKSIDE: 0; Part Type: FERRITE BEAD; SMT: YES
L1 L2 = INDUCTOR_2: 2ND PART FIELD: CV01001KZ45; ANOVO DESCRIPTION: INDUCTOR;10UH,10%,100mA,0805,SMT; ANOVO PART NUMBER: 275001061300; BACKSIDE: 0; Function Code: CLG; NOTE: 3610pcs; Part Number: CV01001KZ45; Part Type: INDUCTOR; SMT: YES
L3 L4 = INDUCTOR: ANOVO DESCRIPTION: INDUCTOR;SMT;1UH;+-10%;50MA;0805;CHILSIN; ANOVO PART NUMBER: 275001050300; BACKSIDE: 0; SMT: YES
L6 = INDUCTOR_5: ANOVO DESCRIPTION: Inductor,100nH,10%,1210,SMT; ANOVO PART NUMBER: 275001041400; Indvctance: 1u; Part Number: CVA9115MN10; Part Type: INDUCTOR; Tolerance: ¢H
C197 PC2 = CAP_T: ANOVO DESCRIPTION: TANCAP,330U,6.3V,20%,D size, SMT; ANOVO PART NUMBER: 272633371011
R111 R112 = R_v2: ANOVO DESCRIPTION: RES;1,1/16W,1%,0402,SMT; ANOVO PART NUMBER: 271040010101
U5 = TMP_160502: ANOVO DESCRIPTION: IC,LE82GME965,GMCH,FBGA,1299B,Intel; ANOVO PART NUMBER: 284508296501; NO_STUFF: .; Part Number: AJ0QK860T13
R87 = R_v2: ANOVO DESCRIPTION: RES;100K ,1/16W ,5% ,0402 ,SMT; ANOVO PART NUMBER: 271040104301; Part Type: RESISTOR
R89 R90 = R_v2: ANOVO DESCRIPTION: RES;1.5K ,1/16W ,5% ,0402 ,SMT; ANOVO PART NUMBER: 271040152301; POWER: 1/16W; Part Type: RESISTOR
R91 = R_0: ANOVO DESCRIPTION: RES;24.9 ,1/16W ,1% ,0402 ,SMT; ANOVO PART NUMBER: 271040249811; Function Code: CLG; POWER: 1/16W; Part Number: CS02492FB29; Part Type: RESISTOR; Size: 0402; Tolerance: 1%; Watt: 1/16W
R93 = R_5: 2ND PART FIELD: CS22402JB15; ANOVO DESCRIPTION: RES;2.4K ,1/10W ,5% ,0603 ,SMT; ANOVO PART NUMBER: 271071242301; BACKSIDE: 0; Function Code: CLG; NOTE: ok; Part Number: CS22402JB15; Part Type: RESISTOR; SMT: YES
R94-R99 = R_0: ANOVO DESCRIPTION: RES;150,1/16W,1%,0402,SMT; ANOVO PART NUMBER: 271040151101; BACKSIDE: 0; Lead Free: EP; Part Type: RESISTOR; Res: 100; SMT: YES; Size: 0402; Tolerance: 1%; Watt: 1/16W
R100 R102 = R_v2: ANOVO DESCRIPTION: RES;30.1 ,1/10W ,1% ,0603 ,SMT; ANOVO PART NUMBER: 271071301811; BACKSIDE: 0; Part Type: resistor; SMT: YES
R101 = R_v2: ANOVO DESCRIPTION: RES;1.3K ,1/10W ,1% ,0603 ,SMT; ANOVO PART NUMBER: 271071132101; BACKSIDE: 0; Part Type: resistor; SMT: YES
CN2 = PC4800_DDR2_6: ANOVO DESCRIPTION: CON;SMT,Slot,Black,200pin,2Row,0.6mm pitch;H9.2,1.8V,standard,SODIMM,Lotes; ANOVO PART NUMBER: 296220200520; Function Code: DDR; Part Number: DG0K0000417; ROOM: DDR2
R120 R122 R124 = R_v2: ANOVO DESCRIPTION: RES,56 ,1/16W ,5%, 0402, SMT; ANOVO PART NUMBER: 271040560301; BACKSIDE: 0; Part Type: RESISTOR
RN1 RN3 RN5 RN7 RN9 RN11 = R_8P4R: NETWORK 56 OHMX4 8PIN 0402 SMT; ANOVO DESCRIPTION: RP;56*4 ,8P ,1/16W ,5% ,0408,SMT; ANOVO PART NUMBER: 271590560301; BACKCOMP: NO; BACKSIDE: NO; ID: 459; Part Type: NETWORK; SMT: YES

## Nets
+1.5V: C182.1 C205.1 R113.1 U5.L29(VCCD_TVDAC) U5.M32(VCCD_CRT) ; also on sheet 6 16 18 32 33
+1.5V_VCCD_QDAC: C185.1 R113.2 U5.N28(VCCD_QDAC)
+1.8V_SM_CK: C160.1 C161.1 L3.1 R111.1 U5.BJ23(VCC_SM_CK_4) U5.BJ24(VCC_SM_CK_3) U5.BK23(VCC_SM_CK_2) U5.BK24(VCC_SM_CK_1)
+1.8V_VCCD_LVDS: C183.1 C184.1 R115.1 U5.H42(VCCD_LVDS_2) U5.J41(VCCD_LVDS_1)
+1.8VSUS: C107.1 C108.2 C110.2 C189.1 C190.1 C191.1 C192.1 C193.1 C194.1 C195.1 C196.1 C197.1 C198.1 C199.1 C200.1 C201.1 C202.1 C203.1 CN2.81(VDD7) CN2.82(VDD8) CN2.87(VDD9) CN2.88(VDD11) CN2.95(VDD5) CN2.96(VDD4) CN2.103(VDD10) CN2.104(VDD12) CN2.111(VDD2) CN2.112(VDD1) CN2.117(VDD3) CN2.118(VDD6) L3.2 L4.2 R63.1 R64.2 R115.2 U5.AU30(VCC_SM_36) U5.AU32(VCC_SM_1) U5.AU33(VCC_SM_2) U5.AU35(VCC_SM_3) U5.AV33(VCC_SM_4) U5.AW33(VCC_SM_5) U5.AW35(VCC_SM_6) U5.AY35(VCC_SM_7) U5.BA32(VCC_SM_8) U5.BA33(VCC_SM_9) U5.BA35(VCC_SM_10) U5.BB33(VCC_SM_11) U5.BC32(VCC_SM_12) U5.BC33(VCC_SM_13) U5.BC35(VCC_SM_14) U5.BD32(VCC_SM_15) U5.BD35(VCC_SM_16) U5.BE32(VCC_SM_17) U5.BE33(VCC_SM_18) U5.BE35(VCC_SM_19) U5.BF33(VCC_SM_20) U5.BF34(VCC_SM_21) U5.BG32(VCC_SM_22) U5.BG33(VCC_SM_23) U5.BG35(VCC_SM_24) U5.BH32(VCC_SM_25) U5.BH34(VCC_SM_26) U5.BH35(VCC_SM_27) U5.BJ32(VCC_SM_28) U5.BJ33(VCC_SM_29) U5.BJ34(VCC_SM_30) U5.BK32(VCC_SM_31) U5.BK33(VCC_SM_32) U5.BK34(VCC_SM_33) U5.BK35(VCC_SM_34) U5.BL33(VCC_SM_35) ; also on sheet 21 32 33 38 39
+1.8VSUS_TX_LVDS: C150.2 C166.1 CT2.1 L4.1 U5.A41(VCCA_LVDS) U5.A43(VCC_TX_LVDS)
+1.25V: C143.1 C144.1 C148.1 C149.2 C153.1 C154.1 C155.1 C156.1 C157.1 C162.1 C163.1 C165.1 FB4.2 FB5.2 FB7.1 L1.1 L2.1 R84.2 R108.2 U5.A21(VCC_AXF_3) U5.AJ50(VCC_DMI) U5.AR16(VCCA_SM_NCTF_2) U5.AR17(VCCA_SM_NCTF_1) U5.AR29(VCC_AXD_NCTF) U5.AT17(VCCA_SM_11) U5.AT18(VCCA_SM_10) U5.AT19(VCCA_SM_9) U5.AT21(VCCA_SM_8) U5.AT22(VCCA_SM_7) U5.AT23(VCC_AXD_1) U5.AT25(VCC_AXD_5) U5.AT29(VCC_AXD_4) U5.AT30(VCC_AXD_6) U5.AU17(VCCA_SM_5) U5.AU18(VCCA_SM_4) U5.AU19(VCCA_SM_3) U5.AU24(VCC_AXD_3) U5.AU28(VCC_AXD_2) U5.AV19(VCCA_SM_2) U5.AW18(VCCA_SM_1) U5.B21(VCC_AXF_2) U5.B23(VCC_AXF_1) U5.BB29(VCCA_SM_CK_2) U5.BC29(VCCA_SM_CK_1) ; also on sheet 18 21 32
+3V: C168.2 FB3.2 R72.1 R73.1 R75.1 R77.2 R78.2 R88.1 R89.1 R90.1 R92.1 R106.2 R107.2 R110.1 R116.1 R117.1 U5.A28(VCCA_TVC_DAC_2) U5.B25(VCCA_TVA_DAC_2) U5.B27(VCCA_TVB_DAC_2) U5.B28(VCCA_TVC_DAC_1) U5.C25(VCCA_TVA_DAC_1) U5.C27(VCCA_TVB_DAC_1) ; also on sheet 4 15 16 17 18 19 20 21 22 23 24 25 26 27 28 31 32 34 35 41
+3V_DUAL: C228.1 CN2.199(VDD(SPD)) ; also on sheet 15 16 17 18 19 20 21 26 31 33 34 38 40 41
+3V_VCCA_CRT_DAC: C135.1 C188.2 C204.1 FB3.1 U5.A33(VCCA_CRT_DAC_1) U5.B33(VCCA_CRT_DAC_2)
+3V_VCCA_DAC_BG: C142.1 R107.1 U5.A30(VCCA_DAC_BG)
+3V_VCCA_PEG_BG: R110.2 U5.K50(VCCA_PEG_BG)
+3V_VCCSYNC: C133.1 R103.1 R106.1 U5.J32(VCCSYNC)
+V1.25_PEG_PLL: C174.1 C180.1 FB7.2 R112.2 U5.U48(VCCD_PEG_PLL) U5.U51(VCCA_PEG_PLL)
+V1.25M_MCH_VCCD_HPLL: C173.1 R108.1 U5.AN2(VCCD_HPLL)
+V3.3S_HV: C169.2 C170.1 R117.2 U5.B40(VCC_HV_2) U5.C40(VCC_HV_1)
+VCC_DMI: C179.2 L6.2 PC2.1 U5.AH50(VCC_RXR_DMI_1) U5.AH51(VCC_RXR_DMI_2)
+VCCP: C103.1 C104.2 C105.2 C106.1 C119.2 C120.2 C121.2 C122.1 C123.1 C124.1 C136.2 C137.2 C138.1 C139.1 C147.1 C172.2 D1.1 D2.1 L6.1 R91.2 R104.1 R118.1 U5.AA33(VCC_NCTF_26) U5.AA35(VCC_NCTF_27) U5.AA36(VCC_NCTF_28) U5.AB33(VCC_NCTF_1) U5.AB36(VCC_NCTF_2) U5.AB37(VCC_NCTF_3) U5.AC31(VCC_4) U5.AC32(VCC_5) U5.AC33(VCC_NCTF_4) U5.AC35(VCC_NCTF_5) U5.AC36(VCC_NCTF_6) U5.AD33(VCC_NCTF_21) U5.AD35(VCC_NCTF_7) U5.AD36(VCC_NCTF_8) U5.AD51(VCC_PEG_1) U5.AF32(VCC_12) U5.AF33(VCC_NCTF_9) U5.AF36(VCC_NCTF_10) U5.AH28(VCC_3) U5.AH29(VCC_11) U5.AH31(VCC_10) U5.AH32(VCC_9) U5.AH33(VCC_NCTF_11) U5.AH35(VCC_NCTF_12) U5.AH36(VCC_NCTF_13) U5.AH37(VCC_NCTF_14) U5.AJ23(VCC_AXM_7) U5.AJ26(VCC_AXM_6) U5.AJ28(VCC_8) U5.AJ31(VCC_7) U5.AJ33(VCC_NCTF_15) U5.AJ35(VCC_NCTF_16) U5.AJ36(VCC_NCTF_22) U5.AK23(VCC_AXM_5) U5.AK24(VCC_AXM_4) U5.AK29(VCC_AXM_3) U5.AK32(VCC_6) U5.AK33(VCC_NCTF_17) U5.AK35(VCC_NCTF_18) U5.AK36(VCC_NCTF_19) U5.AK37(VCC_NCTF_20) U5.AL24(VCC_AXM_NCTF_1) U5.AL26(VCC_AXM_NCTF_2) U5.AL28(VCC_AXM_NCTF_3) U5.AL29(VCC_AXM_NCTF_14) U5.AL31(VCC_AXM_NCTF_15) U5.AL32(VCC_AXM_NCTF_16) U5.AL33(VCC_NCTF_24) U5.AL35(VCC_NCTF_25) U5.AM26(VCC_AXM_NCTF_4) U5.AM28(VCC_AXM_NCTF_5) U5.AM29(VCC_AXM_NCTF_6) U5.AM31(VCC_AXM_NCTF_7) U5.AM32(VCC_AXM_NCTF_8) U5.AM33(VCC_AXM_NCTF_9) U5.AM35(VCC_NCTF_23) U5.AP29(VCC_AXM_NCTF_10) U5.AP31(VCC_AXM_NCTF_11) U5.AP32(VCC_AXM_NCTF_12) U5.AP33(VCC_AXM_NCTF_13) U5.AP35(VCC_NCTF_29) U5.AP36(VCC_NCTF_30) U5.AR31(VCC_AXM_NCTF_17) U5.AR32(VCC_AXM_NCTF_18) U5.AR33(VCC_AXM_NCTF_19) U5.AR35(VCC_NCTF_31) U5.AR36(VCC_NCTF_32) U5.AT31(VCC_AXM_2) U5.AT33(VCC_AXM_1) U5.AT34(VCC_2) U5.AT35(VCC_1) U5.R1(VTT_22) U5.R2(VTT_21) U5.R3(VTT_20) U5.R30(VCC_13) U5.T2(VTT_19) U5.T3(VTT_18) U5.T5(VTT_17) U5.T6(VTT_16) U5.T7(VTT_15) U5.T9(VTT_14) U5.T10(VTT_13) U5.T11(VTT_12) U5.T13(VTT_11) U5.T30(VCC_NCTF_38) U5.T34(VCC_NCTF_39) U5.T35(VCC_NCTF_40) U5.U1(VTT_10) U5.U2(VTT_9) U5.U3(VTT_8) U5.U5(VTT_7) U5.U7(VTT_6) U5.U8(VTT_5) U5.U9(VTT_4) U5.U11(VTT_3) U5.U12(VTT_2) U5.U13(VTT_1) U5.U29(VCC_NCTF_41) U5.U31(VCC_NCTF_42) U5.U32(VCC_NCTF_43) U5.U33(VCC_NCTF_44) U5.U35(VCC_NCTF_45) U5.U36(VCC_NCTF_46) U5.V32(VCC_NCTF_47) U5.V33(VCC_NCTF_48) U5.V36(VCC_NCTF_49) U5.V37(VCC_NCTF_50) U5.V49(VCC_PEG_4) U5.V50(VCC_PEG_5) U5.W50(VCC_PEG_2) U5.W51(VCC_PEG_3) U5.Y32(VCC_NCTF_33) U5.Y33(VCC_NCTF_34) U5.Y35(VCC_NCTF_35) U5.Y36(VCC_NCTF_36) U5.Y37(VCC_NCTF_37) ; also on sheet 5 6 7 15 18 21 31 32
GND: C66.2 C67.1 C68.2 C69.1 C103.2 C104.1 C105.1 C106.2 C107.2 C108.1 C110.1 C111.2 C113.1 C114.2 C115.2 C116.2 C117.2 C119.1 C120.1 C121.1 C122.2 C123.2 C124.2 C125.2 C126.2 C127.2 C128.2 C129.1 C130.2 C131.2 C132.2 C133.2 C134.2 C135.2 C136.1 C137.1 C138.2 C139.2 C140.2 C141.2 C142.2 C143.2 C144.2 C145.2 C146.2 C147.2 C148.2 C149.1 C150.1 C151.2 C152.1 C153.2 C154.2 C155.2 C156.2 C157.2 C159.1 C160.2 C161.2 C162.2 C163.2 C165.2 C166.2 C168.1 C169.1 C170.2 C172.1 C173.2 C174.2 C176.1 C177.1 C178.1 C179.1 C180.2 C181.1 C182.2 C183.2 C184.2 C185.2 C186.2 C188.1 C189.2 C190.2 C191.2 C192.2 C193.2 C194.2 C195.2 C196.2 C197.2 C198.2 C199.2 C200.2 C201.2 C202.2 C203.2 C204.2 C205.2 C206.2 C207.2 C208.2 C209.2 C210.2 C211.2 C212.2 C213.2 C217.2 C218.2 C219.2 C220.2 C221.2 C222.2 C223.2 C224.2 C228.2 CN2.2(VSS46) CN2.3(VSS47) CN2.8(VSS15) CN2.9(VSS37) CN2.12(VSS5) CN2.15(VSS48) CN2.18(VSS16) CN2.21(VSS38) CN2.24(VSS17) CN2.27(VSS49) CN2.28(VSS53) CN2.33(VSS39) CN2.34(VSS41) CN2.39(VSS50) CN2.40(VSS54) CN2.41(VSS18) CN2.42(VSS20) CN2.47(VSS1) CN2.48(VSS6) CN2.53(VSS19) CN2.54(VSS21) CN2.59(VSS22) CN2.60(VSS24) CN2.65(VSS23) CN2.66(VSS25) CN2.71(VSS9) CN2.72(VSS10) CN2.77(VSS4) CN2.78(VSS8) CN2.121(VSS11) CN2.122(VSS12) CN2.127(VSS26) CN2.128(VSS28) CN2.132(VSS42) CN2.133(VSS2) CN2.138(VSS55) CN2.139(VSS27) CN2.144(VSS43) CN2.145(VSS29) CN2.149(VSS51) CN2.150(VSS56) CN2.155(VSS40) CN2.156(VSS44) CN2.161(VSS52) CN2.162(VSS57) CN2.165(VSS30) CN2.168(VSS45) CN2.171(VSS31) CN2.172(VSS32) CN2.177(VSS33) CN2.178(VSS35) CN2.183(VSS3) CN2.184(VSS7) CN2.187(VSS34) CN2.190(VSS36) CN2.193(VSS14) CN2.196(VSS13) CN2.203(GND1) CN2.204(GND2) CT2.2 PC2.2 R66.1 R67.2 R69.2 R70.2 R71.2 R74.2 R76.2 R85.2 R86.2 R87.2 R93.1 R94.1 R95.1 R96.1 R97.1 R98.1 R99.1 R101.1 R127.2 R129.2 U5.A3(VSS_SCB1) U5.A13(VSS_1) U5.A15(VSS_2) U5.A17(VSS_3) U5.A24(VSS_4) U5.A37(TEST_1) U5.A51(VSS_SCB6) U5.AA19(VSS_NCTF_7) U5.AA21(VSS_5) U5.AA24(VSS_6) U5.AA29(VSS_7) U5.AA32(VSS_306) U5.AB17(VSS_NCTF_8) U5.AB20(VSS_8) U5.AB23(VSS_9) U5.AB26(VSS_10) U5.AB28(VSS_11) U5.AB31(VSS_12) U5.AB32(VSS_307) U5.AB35(VSS_NCTF_9) U5.AC3(VSS_15) U5.AC10(VSS_13) U5.AC13(VSS_14) U5.AC39(VSS_16) U5.AC43(VSS_17) U5.AC47(VSS_18) U5.AD1(VSS_19) U5.AD3(VSS_23) U5.AD5(VSS_27) U5.AD8(VSS_29) U5.AD19(VSS_NCTF_10) U5.AD21(VSS_20) U5.AD26(VSS_21) U5.AD29(VSS_22) U5.AD32(VSS_308) U5.AD37(VSS_NCTF_11) U5.AD41(VSS_24) U5.AD45(VSS_25) U5.AD49(VSS_26) U5.AD50(VSS_28) U5.AE6(VSS_32) U5.AE10(VSS_30) U5.AE14(VSS_31) U5.AF17(VSS_NCTF_12) U5.AF20(VSS_33) U5.AF23(VSS_34) U5.AF24(VSS_35) U5.AF28(VSS_309) U5.AF29(VSS_310) U5.AF31(VSS_36) U5.AF35(VSS_NCTF_13) U5.AG2(VSS_37) U5.AG38(VSS_38) U5.AG43(VSS_39) U5.AG47(VSS_40) U5.AG50(VSS_41) U5.AH3(VSS_42) U5.AH7(VSS_45) U5.AH9(VSS_46) U5.AH40(VSS_43) U5.AH41(VSS_44) U5.AJ11(VSS_47) U5.AJ13(VSS_48) U5.AJ21(VSS_49) U5.AJ24(VSS_50) U5.AJ29(VSS_51) U5.AJ32(VSS_52) U5.AJ43(VSS_53) U5.AJ45(VSS_54) U5.AJ49(VSS_55) U5.AK17(VSS_NCTF_14) U5.AK20(VSS_56) U5.AK21(VSS_57) U5.AK26(VSS_58) U5.AK28(VSS_59) U5.AK31(VSS_60) U5.AK51(VSS_61) U5.AL1(VSS_62) U5.AM3(VSS_65) U5.AM4(VSS_66) U5.AM11(VSS_63) U5.AM13(VSS_64) U5.AM17(VSS_NCTF_15) U5.AM24(VSS_NCTF_16) U5.AM41(VSS_67) U5.AM45(VSS_68) U5.AN1(VSS_69) U5.AN5(VSS_73) U5.AN7(VSS_74) U5.AN38(VSS_70) U5.AN39(VSS_71) U5.AN43(VSS_72) U5.AP4(VSS_75) U5.AP26(VSS_NCTF_17) U5.AP28(VSS_NCTF_18) U5.AP48(VSS_76) U5.AP50(VSS_77) U5.AR2(VSS_79) U5.AR7(VSS_83) U5.AR11(VSS_78) U5.AR15(VSS_NCTF_19) U5.AR19(VSS_NCTF_20) U5.AR28(VSS_NCTF_21) U5.AR39(VSS_80) U5.AR44(VSS_81) U5.AR47(VSS_82) U5.AT10(VSS_84) U5.AT14(VSS_85) U5.AT27(VSS_311) U5.AT41(VSS_86) U5.AT49(VSS_87) U5.AU1(VSS_88) U5.AU3(VSS_91) U5.AU23(VSS_89) U5.AU29(VSS_90) U5.AU36(VSS_92) U5.AU49(VSS_93) U5.AU51(VSS_94) U5.AV25(VSS_312) U5.AV39(VSS_95) U5.AV48(VSS_96) U5.AW1(VSS_97) U5.AW5(VSS_103) U5.AW7(VSS_104) U5.AW12(VSS_98) U5.AW16(VSS_99) U5.AW24(VSS_100) U5.AW29(VSS_101) U5.AW32(VSS_102) U5.AY10(VSS_105) U5.AY24(VSS_106) U5.AY37(VSS_107) U5.AY42(VSS_108) U5.AY43(VSS_109) U5.AY45(VSS_110) U5.AY47(VSS_111) U5.AY50(VSS_112) U5.B2(VSS_SCB2) U5.B5(VSS_122) U5.B8(VSS_123) U5.B10(VSS_113) U5.B20(VSS_114) U5.B24(VSS_115) U5.B29(VSS_116) U5.B30(VSS_117) U5.B32(VSSA_DAC_BG) U5.B35(VSS_118) U5.B38(VSS_119) U5.B41(VSSA_LVDS) U5.B43(VSS_120) U5.B46(VSS_121) U5.BA1(VSS_124) U5.BA2(VSS_127) U5.BA17(VSS_125) U5.BA18(VSS_126) U5.BA24(VSS_128) U5.BB8(VSS_134) U5.BB12(VSS_129) U5.BB25(VSS_130) U5.BB40(VSS_131) U5.BB44(VSS_132) U5.BB49(VSS_133) U5.BC16(VSS_135) U5.BC24(VSS_136) U5.BC25(VSS_137) U5.BC36(VSS_138) U5.BC40(VSS_139) U5.BC51(VSS_140) U5.BD2(VSS_142) U5.BD5(VSS_146) U5.BD13(VSS_141) U5.BD28(VSS_143) U5.BD45(VSS_144) U5.BD48(VSS_145) U5.BE1(VSS_147) U5.BE8(VSS_153) U5.BE19(VSS_148) U5.BE23(VSS_149) U5.BE30(VSS_150) U5.BE42(VSS_151) U5.BE51(VSS_152) U5.BF12(VSS_154) U5.BF16(VSS_155) U5.BF36(VSS_156) U5.BG2(VSS_158) U5.BG5(VSS_163) U5.BG19(VSS_157) U5.BG24(VSS_159) U5.BG29(VSS_160) U5.BG39(VSS_161) U5.BG48(VSS_162) U5.BG51(VSS_164) U5.BH8(VSS_169) U5.BH17(VSS_165) U5.BH30(VSS_166) U5.BH44(VSS_167) U5.BH46(VSS_168) U5.BJ4(VSS_173) U5.BJ11(VSS_170) U5.BJ13(VSS_171) U5.BJ38(VSS_172) U5.BJ42(VSS_174) U5.BJ46(VSS_175) U5.BK6(VSS_183) U5.BK8(VSS_184) U5.BK15(VSS_176) U5.BK17(VSS_177) U5.BK25(VSS_178) U5.BK29(VSS_179) U5.BK36(VSS_180) U5.BK40(VSS_181) U5.BK44(VSS_182) U5.BL1(VSS_SCB4) U5.BL11(VSS_185) U5.BL13(VSS_186) U5.BL19(VSS_187) U5.BL22(VSS_188) U5.BL37(VSS_189) U5.BL47(VSS_190) U5.BL51(VSS_SCB5) U5.C1(VSS_SCB3) U5.C7(VSS_201) U5.C12(VSS_191) U5.C16(VSS_192) U5.C19(VSS_193) U5.C28(VSS_194) U5.C29(VSS_195) U5.C33(VSS_196) U5.C36(VSS_197) U5.C41(VSS_198) U5.C46(VSS_199) U5.C50(VSS_200) U5.D3(VSS_204) U5.D13(VSS_202) U5.D24(VSS_203) U5.D32(VSS_205) U5.D39(VSS_206) U5.D45(VSS_207) U5.D49(VSS_208) U5.E10(VSS_209) U5.E16(VSS_210) U5.E24(VSS_211) U5.E28(VSS_212) U5.E29(CRT_RED#) U5.E32(VSS_213) U5.E47(VSS_214) U5.F4(VSS_217) U5.F19(VSS_215) U5.F27(TVA_RTN) U5.F36(VSS_216) U5.F40(VSS_218) U5.F50(VSS_219) U5.G1(VSS_220) U5.G8(VSS_231) U5.G13(VSS_221) U5.G16(VSS_222) U5.G19(VSS_223) U5.G24(VSS_224) U5.G28(VSS_225) U5.G29(VSS_226) U5.G32(CRT_BLUE#) U5.G33(VSS_227) U5.G42(VSS_228) U5.G45(VSS_229) U5.G48(VSS_230) U5.H4(VSS_234) U5.H24(VSS_232) U5.H28(VSS_233) U5.H45(VSS_235) U5.H50(VSS_313) U5.J2(VSS_238) U5.J11(VSS_236) U5.J16(VSS_237) U5.J24(VSS_239) U5.J27(TVB_RTN) U5.J28(VSS_240) U5.J29(CRT_GREEN#) U5.J33(VSS_241) U5.J35(VSS_242) U5.J39(VSS_243) U5.K8(VSS_247) U5.K12(VSS_245) U5.K47(VSS_246) U5.K49(VSSA_PEG_BG) U5.L1(VSS_248) U5.L3(VSS_253) U5.L17(VSS_249) U5.L20(VSS_250) U5.L24(VSS_251) U5.L27(TVC_RTN) U5.L28(VSS_252) U5.L33(VSS_254) U5.L49(VSS_255) U5.M5(VSS_260) U5.M9(VSS_262) U5.M28(VSS_256) U5.M42(VSS_257) U5.M46(VSS_258) U5.M49(VSS_259) U5.M50(VSS_261) U5.N7(VSS_272) U5.N11(VSS_263) U5.N14(VSS_264) U5.N17(VSS_265) U5.N29(VSS_266) U5.N32(VSS_267) U5.N36(VSS_268) U5.N39(VSS_269) U5.N40(LVDS_VREFL) U5.N41(LVDS_VREFH) U5.N44(VSS_270) U5.N49(VSS_271) U5.P2(VSS_274) U5.P3(VSS_276) U5.P19(VSS_273) U5.P23(VSS_275) U5.P29(VSS_301) U5.P50(VSS_277) U5.R28(VSS_305) U5.R49(VSS_278) U5.T27(VSS_NCTF_1) U5.T29(VSS_302) U5.T31(VSS_303) U5.T33(VSS_304) U5.T37(VSS_NCTF_2) U5.T39(VSS_279) U5.T43(VSS_280) U5.T47(VSS_281) U5.U24(VSS_NCTF_3) U5.U28(VSS_NCTF_4) U5.U41(VSS_282) U5.U45(VSS_283) U5.U50(VSS_284) U5.V2(VSS_285) U5.V3(VSS_286) U5.V31(VSS_NCTF_5) U5.V35(VSS_NCTF_6) U5.W5(VSS_291) U5.W7(VSS_292) U5.W11(VSS_287) U5.W39(VSS_288) U5.W43(VSS_289) U5.W47(VSS_290) U5.Y2(VSS_294) U5.Y5(VSS_298) U5.Y11(VSS_300) U5.Y13(VSS_293) U5.Y41(VSS_295) U5.Y45(VSS_296) U5.Y49(VSS_297) U5.Y50(VSS_299) ; also on sheet 4 5 6 7 15 16 17 18 19 20 21 22 23 24 25 26 27 28 29 30 31 32 33 34 35 36 37 38 39 40 41
V1.25M_MPLL_RC: C152.2 R109.1
VCCA_DPLLA: C132.1 C134.1 L1.2 U5.B49(VCCA_DPLLA)
VCCA_DPLLB: C140.1 C141.1 L2.2 U5.H49(VCCA_DPLLB)
VCCA_HPLL: C145.1 C146.1 FB4.1 U5.AL2(VCCA_HPLL)
VCCA_MPLL: C151.1 FB5.1 R109.2 U5.AM2(VCCA_MPLL)
+VGFX_CORE: C111.1 C113.2 C114.1 C115.1 C116.1 C117.1 R104.2 R118.2 U5.AA16(VCC_AXG_NCTF_34) U5.AA17(VCC_AXG_NCTF_35) U5.AA20(VCC_AXG_6) U5.AA23(VCC_AXG_7) U5.AA26(VCC_AXG_8) U5.AA28(VCC_AXG_9) U5.AA31(VCC_AXG_26) U5.AB16(VCC_AXG_NCTF_36) U5.AB19(VCC_AXG_NCTF_37) U5.AB21(VCC_AXG_10) U5.AB24(VCC_AXG_11) U5.AB29(VCC_AXG_12) U5.AC16(VCC_AXG_NCTF_38) U5.AC17(VCC_AXG_NCTF_39) U5.AC19(VCC_AXG_NCTF_40) U5.AC20(VCC_AXG_13) U5.AC21(VCC_AXG_14) U5.AC23(VCC_AXG_15) U5.AC24(VCC_AXG_16) U5.AC26(VCC_AXG_17) U5.AC28(VCC_AXG_18) U5.AC29(VCC_AXG_19) U5.AD15(VCC_AXG_NCTF_41) U5.AD16(VCC_AXG_NCTF_42) U5.AD17(VCC_AXG_NCTF_43) U5.AD20(VCC_AXG_20) U5.AD23(VCC_AXG_21) U5.AD24(VCC_AXG_22) U5.AD28(VCC_AXG_23) U5.AD31(VCC_AXG_32) U5.AF16(VCC_AXG_NCTF_44) U5.AF19(VCC_AXG_NCTF_45) U5.AF21(VCC_AXG_24) U5.AF26(VCC_AXG_25) U5.AH15(VCC_AXG_NCTF_46) U5.AH16(VCC_AXG_NCTF_47) U5.AH17(VCC_AXG_NCTF_48) U5.AH19(VCC_AXG_NCTF_49) U5.AH20(VCC_AXG_27) U5.AH21(VCC_AXG_28) U5.AH23(VCC_AXG_29) U5.AH24(VCC_AXG_30) U5.AH26(VCC_AXG_31) U5.AJ16(VCC_AXG_NCTF_50) U5.AJ17(VCC_AXG_NCTF_51) U5.AJ19(VCC_AXG_NCTF_52) U5.AJ20(VCC_AXG_33) U5.AK16(VCC_AXG_NCTF_53) U5.AK19(VCC_AXG_NCTF_54) U5.AL16(VCC_AXG_NCTF_55) U5.AL17(VCC_AXG_NCTF_56) U5.AL19(VCC_AXG_NCTF_57) U5.AL20(VCC_AXG_NCTF_58) U5.AL21(VCC_AXG_NCTF_59) U5.AL23(VCC_AXG_NCTF_60) U5.AM15(VCC_AXG_NCTF_61) U5.AM16(VCC_AXG_NCTF_62) U5.AM19(VCC_AXG_NCTF_63) U5.AM20(VCC_AXG_NCTF_64) U5.AM21(VCC_AXG_NCTF_65) U5.AM23(VCC_AXG_NCTF_66) U5.AN14(VCC_AXG_34) U5.AP15(VCC_AXG_NCTF_67) U5.AP16(VCC_AXG_NCTF_68) U5.AP17(VCC_AXG_NCTF_69) U5.AP19(VCC_AXG_NCTF_70) U5.AP20(VCC_AXG_NCTF_71) U5.AP21(VCC_AXG_NCTF_72) U5.AP23(VCC_AXG_NCTF_73) U5.AP24(VCC_AXG_NCTF_74) U5.AR20(VCC_AXG_NCTF_75) U5.AR21(VCC_AXG_NCTF_76) U5.AR23(VCC_AXG_NCTF_77) U5.AR24(VCC_AXG_NCTF_78) U5.AR26(VCC_AXG_NCTF_79) U5.R20(VCC_AXG_1) U5.T14(VCC_AXG_2) U5.T17(VCC_AXG_NCTF_1) U5.T18(VCC_AXG_NCTF_2) U5.T19(VCC_AXG_NCTF_3) U5.T21(VCC_AXG_NCTF_4) U5.T22(VCC_AXG_NCTF_5) U5.T23(VCC_AXG_NCTF_6) U5.T25(VCC_AXG_NCTF_7) U5.U15(VCC_AXG_NCTF_8) U5.U16(VCC_AXG_NCTF_9) U5.U17(VCC_AXG_NCTF_10) U5.U19(VCC_AXG_NCTF_11) U5.U20(VCC_AXG_NCTF_12) U5.U21(VCC_AXG_NCTF_13) U5.U23(VCC_AXG_NCTF_14) U5.U26(VCC_AXG_NCTF_15) U5.V16(VCC_AXG_NCTF_16) U5.V17(VCC_AXG_NCTF_17) U5.V19(VCC_AXG_NCTF_18) U5.V20(VCC_AXG_NCTF_19) U5.V21(VCC_AXG_NCTF_20) U5.V23(VCC_AXG_NCTF_21) U5.V24(VCC_AXG_NCTF_22) U5.V26(VCC_AXG_NCTF_80) U5.V28(VCC_AXG_NCTF_81) U5.V29(VCC_AXG_NCTF_82) U5.W13(VCC_AXG_3) U5.W14(VCC_AXG_4) U5.Y12(VCC_AXG_5) U5.Y15(VCC_AXG_NCTF_23) U5.Y16(VCC_AXG_NCTF_24) U5.Y17(VCC_AXG_NCTF_25) U5.Y19(VCC_AXG_NCTF_26) U5.Y20(VCC_AXG_NCTF_27) U5.Y21(VCC_AXG_NCTF_28) U5.Y23(VCC_AXG_NCTF_29) U5.Y24(VCC_AXG_NCTF_30) U5.Y26(VCC_AXG_NCTF_31) U5.Y28(VCC_AXG_NCTF_32) U5.Y29(VCC_AXG_NCTF_33) U5.Y31(VCC_AXG_NCTF_83)
BL_CTRL: U5.J40(L_BKLT_CTRL) ; also on sheet 30
C_PEG_TXN0: C70.1 U5.N45(PEG_TX#_0)
C_PEG_TXN1: C71.1 U5.U39(PEG_TX#_1)
C_PEG_TXN2: C72.1 U5.U47(PEG_TX#_2)
C_PEG_TXN3: C73.1 U5.N51(PEG_TX#_3)
C_PEG_TXP0: C86.1 U5.M45(PEG_TX_0)
C_PEG_TXP1: C87.1 U5.T38(PEG_TX_1)
C_PEG_TXP2: C88.1 U5.T46(PEG_TX_2)
C_PEG_TXP3: C89.1 U5.N50(PEG_TX_3)
CGCLK_SMB: CN2.197(SCL) ; also on sheet 4 38
CGDAT_SMB: CN2.195(SDA) ; also on sheet 4 38
CL_CLK0: U5.AM49(CL_CLK) ; also on sheet 17
CL_DATA0: U5.AK50(CL_DATA) ; also on sheet 17
CL_RST#0: U5.AN49(CL_RST#) ; also on sheet 17
CL_VREF: R84.1 R85.1 U5.AM50(CL_VREF)
CLK_MCH_OE#: R72.2 U5.G39(CLK_REQ#)
CLK_PCIE_3GPLL: U5.K44(PEG_CLK) ; also on sheet 4
CLK_PCIE_3GPLL#: U5.K45(PEG_CLK#) ; also on sheet 4
CPU_DPRSTP#: R79.2 U5.L39(PM_DPRSTP#) ; also on sheet 5
CRTDCLK: U5.K33(CRT_DDC_CLK) ; also on sheet 26
CRTDDAT: U5.G35(CRT_DDC_DATA) ; also on sheet 26
CRTHSYNC: R100.1 ; also on sheet 26
CRTIREF: R101.2 U5.C32(CRT_TVO_IREF)
CRTVSYNC: R102.1 ; also on sheet 26
DMI_RXN0: U5.AJ46(DMI_TXN_0) ; also on sheet 16
DMI_RXN1: U5.AJ41(DMI_TXN_1) ; also on sheet 16
DMI_RXN2: U5.AM40(DMI_TXN_2) ; also on sheet 16
DMI_RXN3: U5.AM44(DMI_TXN_3) ; also on sheet 16
DMI_RXP0: U5.AJ47(DMI_TXP_0) ; also on sheet 16
DMI_RXP1: U5.AJ42(DMI_TXP_1) ; also on sheet 16
DMI_RXP2: U5.AM39(DMI_TXP_2) ; also on sheet 16
DMI_RXP3: U5.AM43(DMI_TXP_3) ; also on sheet 16
DMI_TXN0: U5.AN47(DMI_RXN_0) ; also on sheet 16
DMI_TXN1: U5.AJ38(DMI_RXN_1) ; also on sheet 16
DMI_TXN2: U5.AN42(DMI_RXN_2) ; also on sheet 16
DMI_TXN3: U5.AN46(DMI_RXN_3) ; also on sheet 16
DMI_TXP0: U5.AM47(DMI_RXP_0) ; also on sheet 16
DMI_TXP1: U5.AJ39(DMI_RXP_1) ; also on sheet 16
DMI_TXP2: U5.AN41(DMI_RXP_2) ; also on sheet 16
DMI_TXP3: U5.AN45(DMI_RXP_3) ; also on sheet 16
DREFCLK: U5.B42(DPLL_REF_CLK) ; also on sheet 4
DREFCLK#: U5.C42(DPLL_REF_CLK#) ; also on sheet 4
DREFSSCLK: U5.H48(DPLL_REF_SSCLK) ; also on sheet 4
DREFSSCLK#: U5.H47(DPLL_REF_SSCLK#) ; also on sheet 4
EXP_A_COMP: R91.1 U5.M43(PEG_COMPO) U5.N43(PEG_COMPI)
INT_CRTHSYNC: R100.2 U5.F33(CRT_HSYNC)
INT_CRTVSYNC: R102.2 U5.E33(CRT_VSYNC)
LCD_CLKCTLA: R92.2 U5.E39(L_CTRL_CLK)
LCD_CLKCTLB: R88.2 U5.E40(L_CTRL_DATA)
LCD_EDIDCLK: R89.2 U5.C37(L_DDC_CLK)
LCD_EDIDDAT: R90.2 U5.D35(L_DDC_DATA)
LCD_ON: U5.K40(L_VDD_EN) ; also on sheet 25
LVDS_TXL0+: U5.G50(LVDSA_DATA_0) ; also on sheet 30
LVDS_TXL0-: U5.G51(LVDSA_DATA#_0) ; also on sheet 30
LVDS_TXL0N: U5.G44(LVDSB_DATA#_0) ; also on sheet 30
LVDS_TXL0P: U5.E44(LVDSB_DATA_0) ; also on sheet 30
LVDS_TXL1+: U5.E50(LVDSA_DATA_1) ; also on sheet 30
LVDS_TXL1-: U5.E51(LVDSA_DATA#_1) ; also on sheet 30
LVDS_TXL1N: U5.B47(LVDSB_DATA#_1) ; also on sheet 30
LVDS_TXL1P: U5.A47(LVDSB_DATA_1) ; also on sheet 30
LVDS_TXL2+: U5.F48(LVDSA_DATA_2) ; also on sheet 30
LVDS_TXL2-: U5.F49(LVDSA_DATA#_2) ; also on sheet 30
LVDS_TXL2N: U5.B45(LVDSB_DATA#_2) ; also on sheet 30
LVDS_TXL2P: U5.A45(LVDSB_DATA_2) ; also on sheet 30
LVDS_TXL3+: U5.D47(RSVD38) ; also on sheet 30
LVDS_TXL3-: U5.C48(RSVD37) ; also on sheet 30
LVDS_TXL3N: U5.B44(RSVD39) ; also on sheet 30
LVDS_TXL3P: U5.C44(RSVD40) ; also on sheet 30
LVDS_TXLCK+: U5.C45(LVDSA_CLK) ; also on sheet 30
LVDS_TXLCK-: U5.D46(LVDSA_CLK#) ; also on sheet 30
LVDS_TXLCKN: U5.D44(LVDSB_CLK#) ; also on sheet 30
LVDS_TXLCKP: U5.E42(LVDSB_CLK) ; also on sheet 30
M_A_A0: CN2.102(A0) RN9.7(R41) ; also on sheet 8
M_A_A1: CN2.101(A1) RN3.1(R11) ; also on sheet 8
M_A_A2: CN2.100(A2) RN9.5(R31) ; also on sheet 8
M_A_A3: CN2.99(A3) RN3.3(R21) ; also on sheet 8
M_A_A4: CN2.98(A4) RN9.3(R21) ; also on sheet 8
M_A_A5: CN2.97(A5) RN3.5(R31) ; also on sheet 8
M_A_A6: CN2.94(A6) RN9.1(R11) ; also on sheet 8
M_A_A7: CN2.92(A7) RN7.7(R41) ; also on sheet 8
M_A_A8: CN2.93(A8) RN3.7(R41) ; also on sheet 8
M_A_A9: CN2.91(A9) RN1.1(R11) ; also on sheet 8
M_A_A10: CN2.105(A10/AP) RN5.7(R41) ; also on sheet 8
M_A_A11: CN2.90(A11) RN7.5(R31) ; also on sheet 8
M_A_A12: CN2.89(A12) RN1.3(R21) ; also on sheet 8
M_A_A13: CN2.116(A13) R124.1 ; also on sheet 8
M_A_A14: CN2.86(A14) RN7.3(R21) U5.BJ29(SA_MA14)
M_A_BS#0: CN2.107(BA0) RN5.5(R31) ; also on sheet 8
M_A_BS#1: CN2.106(BA1) RN11.1(R11) ; also on sheet 8
M_A_BS#2: CN2.85(A16_BA2) RN1.5(R31) ; also on sheet 8
M_A_CAS#: CN2.113(CAS#) RN5.1(R11) ; also on sheet 8
M_A_DM0: CN2.10(DM0) ; also on sheet 8
M_A_DM1: CN2.26(DM1) ; also on sheet 8
M_A_DM2: CN2.52(DM2) ; also on sheet 8
M_A_DM3: CN2.67(DM3) ; also on sheet 8
M_A_DM4: CN2.130(DM4) ; also on sheet 8
M_A_DM5: CN2.147(DM5) ; also on sheet 8
M_A_DM6: CN2.170(DM6) ; also on sheet 8
M_A_DM7: CN2.185(DM7) ; also on sheet 8
M_A_DQ0: CN2.5(DQ0) ; also on sheet 8
M_A_DQ1: CN2.7(DQ1) ; also on sheet 8
M_A_DQ2: CN2.17(DQ2) ; also on sheet 8
M_A_DQ3: CN2.19(DQ3) ; also on sheet 8
M_A_DQ4: CN2.6(DQ5) ; also on sheet 8
M_A_DQ5: CN2.4(DQ4) ; also on sheet 8
M_A_DQ6: CN2.14(DQ6) ; also on sheet 8
M_A_DQ7: CN2.16(DQ7) ; also on sheet 8
M_A_DQ8: CN2.23(DQ8) ; also on sheet 8
M_A_DQ9: CN2.25(DQ9) ; also on sheet 8
M_A_DQ10: CN2.37(DQ11) ; also on sheet 8
M_A_DQ11: CN2.35(DQ10) ; also on sheet 8
M_A_DQ12: CN2.20(DQ12) ; also on sheet 8
M_A_DQ13: CN2.22(DQ13) ; also on sheet 8
M_A_DQ14: CN2.36(DQ14) ; also on sheet 8
M_A_DQ15: CN2.38(DQ15) ; also on sheet 8
M_A_DQ16: CN2.45(DQ17) ; also on sheet 8
M_A_DQ17: CN2.43(DQ16) ; also on sheet 8
M_A_DQ18: CN2.55(DQ18) ; also on sheet 8
M_A_DQ19: CN2.57(DQ19) ; also on sheet 8
M_A_DQ20: CN2.44(DQ20) ; also on sheet 8
M_A_DQ21: CN2.46(DQ21) ; also on sheet 8
M_A_DQ22: CN2.56(DQ22) ; also on sheet 8
M_A_DQ23: CN2.58(DQ23) ; also on sheet 8
M_A_DQ24: CN2.61(DQ24) ; also on sheet 8
M_A_DQ25: CN2.63(DQ25) ; also on sheet 8
M_A_DQ26: CN2.73(DQ26) ; also on sheet 8
M_A_DQ27: CN2.75(DQ27) ; also on sheet 8
M_A_DQ28: CN2.62(DQ28) ; also on sheet 8
M_A_DQ29: CN2.64(DQ29) ; also on sheet 8
M_A_DQ30: CN2.74(DQ30) ; also on sheet 8
M_A_DQ31: CN2.76(DQ31) ; also on sheet 8
M_A_DQ32: CN2.123(DQ32) ; also on sheet 8
M_A_DQ33: CN2.125(DQ33) ; also on sheet 8
M_A_DQ34: CN2.137(DQ35) ; also on sheet 8
M_A_DQ35: CN2.135(DQ34) ; also on sheet 8
M_A_DQ36: CN2.124(DQ36) ; also on sheet 8
M_A_DQ37: CN2.126(DQ37) ; also on sheet 8
M_A_DQ38: CN2.134(DQ38) ; also on sheet 8
M_A_DQ39: CN2.136(DQ39) ; also on sheet 8
M_A_DQ40: CN2.141(DQ40) ; also on sheet 8
M_A_DQ41: CN2.143(DQ41) ; also on sheet 8
M_A_DQ42: CN2.153(DQ43) ; also on sheet 8
M_A_DQ43: CN2.152(DQ46) ; also on sheet 8
M_A_DQ44: CN2.140(DQ44) ; also on sheet 8
M_A_DQ45: CN2.142(DQ45) ; also on sheet 8
M_A_DQ46: CN2.154(DQ47) ; also on sheet 8
M_A_DQ47: CN2.151(DQ42) ; also on sheet 8
M_A_DQ48: CN2.160(DQ53) ; also on sheet 8
M_A_DQ49: CN2.158(DQ52) ; also on sheet 8
M_A_DQ50: CN2.173(DQ50) ; also on sheet 8
M_A_DQ51: CN2.175(DQ51) ; also on sheet 8
M_A_DQ52: CN2.157(DQ48) ; also on sheet 8
M_A_DQ53: CN2.159(DQ49) ; also on sheet 8
M_A_DQ54: CN2.176(DQ55) ; also on sheet 8
M_A_DQ55: CN2.174(DQ54) ; also on sheet 8
M_A_DQ56: CN2.179(DQ56) ; also on sheet 8
M_A_DQ57: CN2.181(DQ57) ; also on sheet 8
M_A_DQ58: CN2.189(DQ58) ; also on sheet 8
M_A_DQ59: CN2.191(DQ59) ; also on sheet 8
M_A_DQ60: CN2.180(DQ60) ; also on sheet 8
M_A_DQ61: CN2.182(DQ61) ; also on sheet 8
M_A_DQ62: CN2.192(DQ62) ; also on sheet 8
M_A_DQ63: CN2.194(DQ63) ; also on sheet 8
M_A_DQS0: CN2.13(DQS0) ; also on sheet 8
M_A_DQS1: CN2.31(DQS1) ; also on sheet 8
M_A_DQS2: CN2.51(DQS2) ; also on sheet 8
M_A_DQS3: CN2.70(DQS3) ; also on sheet 8
M_A_DQS4: CN2.131(DQS4) ; also on sheet 8
M_A_DQS5: CN2.148(DQS5) ; also on sheet 8
M_A_DQS6: CN2.169(DQS6) ; also on sheet 8
M_A_DQS7: CN2.188(DQS7) ; also on sheet 8
M_A_DQS#0: CN2.11(DQS#0) ; also on sheet 8
M_A_DQS#1: CN2.29(DQS#1) ; also on sheet 8
M_A_DQS#2: CN2.49(DQS#2) ; also on sheet 8
M_A_DQS#3: CN2.68(DQS#3) ; also on sheet 8
M_A_DQS#4: CN2.129(DQS#4) ; also on sheet 8
M_A_DQS#5: CN2.146(DQS#5) ; also on sheet 8
M_A_DQS#6: CN2.167(DQS#6) ; also on sheet 8
M_A_DQS#7: CN2.186(DQS#7) ; also on sheet 8
M_A_RAS#: CN2.108(RAS#) RN11.3(R21) ; also on sheet 8
M_A_WE#: CN2.109(WE#) RN5.3(R21) ; also on sheet 8
M_B_A14: U5.BE24(SB_MA14)
M_CKE0: CN2.79(CKE0) RN1.7(R41) U5.BE29(SM_CKE_0)
M_CKE1: CN2.80(CKE1) RN7.1(R11) U5.AY32(SM_CKE_1)
M_CKE2: U5.BD39(SM_CKE_3) ; also on sheet 37
M_CKE3: U5.BG37(SM_CKE_4) ; also on sheet 37
M_CLK_DDR0: CN2.30(CK0) U5.AV29(SM_CK_0)
M_CLK_DDR0#: CN2.32(CK0#) U5.AW30(SM_CK#_0)
M_CLK_DDR1: CN2.164(CK1) U5.BB23(SM_CK_1)
M_CLK_DDR1#: CN2.166(CK1#) U5.BA23(SM_CK#_1)
M_CLK_DDR2: U5.BA25(SM_CK_3) ; also on sheet 38 39
M_CLK_DDR2#: U5.AW25(SM_CK#_3) ; also on sheet 38 39
M_CLK_DDR3: U5.AV23(SM_CK_4) ; also on sheet 38 39
M_CLK_DDR3#: U5.AW23(SM_CK#_4) ; also on sheet 38 39
M_CS#0: CN2.110(S0#) RN11.5(R31) U5.BG20(SM_CS#_0)
M_CS#1: CN2.115(S1#) R120.1 U5.BK16(SM_CS#_1)
M_CS#2: U5.BG16(SM_CS#_2) ; also on sheet 37
M_CS#3: U5.BE13(SM_CS#_3) ; also on sheet 37
M_ODT0: CN2.114(ODT0) RN11.7(R41) U5.BH18(SM_ODT_0)
M_ODT1: CN2.119(ODT1) R122.1 U5.BJ15(SM_ODT_1)
M_ODT2: U5.BJ14(SM_ODT_2) ; also on sheet 37
M_ODT3: U5.BE16(SM_ODT_3) ; also on sheet 37
M_RCOMP: R64.1 U5.BL15(SM_RCOMP)
M_RCOMP#: R66.2 U5.BK14(SM_RCOMP#)
MCH_BSEL0: U5.P27(CFG_0) ; also on sheet 4
MCH_BSEL1: U5.N27(CFG_1) ; also on sheet 4
MCH_BSEL2: U5.N24(CFG_2) ; also on sheet 4
MCH_CFG_3: T15.1 U5.C21(CFG_3)
MCH_CFG_4: T16.1 U5.C23(CFG_4)
MCH_CFG_5: R69.1 U5.F23(CFG_5)
MCH_CFG_6: T17.1 U5.N23(CFG_6)
MCH_CFG_7: T18.1 U5.G23(CFG_7)
MCH_CFG_8: T19.1 U5.J20(CFG_8)
MCH_CFG_9: R70.1 U5.C20(CFG_9)
MCH_CFG_10: T20.1 U5.R24(CFG_10)
MCH_CFG_11: T21.1 U5.L23(CFG_11)
MCH_CFG_12: R71.1 U5.J23(CFG_12)
MCH_CFG_13: R74.1 U5.E23(CFG_13)
MCH_CFG_14: T22.1 U5.E20(CFG_14)
MCH_CFG_15: T23.1 U5.K23(CFG_15)
MCH_CFG_16: R76.1 U5.M20(CFG_16)
MCH_CFG_17: T24.1 U5.M24(CFG_17)
MCH_CFG_18: T25.1 U5.L32(CFG_18)
MCH_CFG_19: R77.1 U5.N33(CFG_19)
MCH_CFG_20: R78.1 U5.L35(CFG_20)
MCH_DPRSTP#: R79.1 ; also on sheet 31
MCH_ICH_SYNC: U5.G40(ICH_SYNC#) ; also on sheet 17
MPWROK: U5.AT43(CL_PWROK) ; also on sheet 17 31
PEG_RXN1: U5.L51(PEG_RX#_1) ; also on sheet 35
PEG_RXP1: U5.L50(PEG_RX_1) ; also on sheet 35
PEG_TXN0: C70.2 ; also on sheet 35
PEG_TXN1: C71.2 ; also on sheet 35
PEG_TXN2: C72.2 ; also on sheet 35
PEG_TXN3: C73.2 ; also on sheet 35
PEG_TXP0: C86.2 ; also on sheet 35
PEG_TXP1: C87.2 ; also on sheet 35
PEG_TXP2: C88.2 ; also on sheet 35
PEG_TXP3: C89.2 ; also on sheet 35
PLT_RST-R#: R82.2 ; also on sheet 16
PM_BMBUSY#: U5.G41(PM_BM_BUSY#) ; also on sheet 17
PM_DPRSLPVR: U5.G36(DPRSLPVR) ; also on sheet 17 31
PM_EXTTS#0: CN2.50(NC3) R73.2 R80.1
PM_EXTTS#1: R75.2 R81.1
PM_THRMTRIP#: R83.1 ; also on sheet 5 15
PWROK: U5.AW49(PWROK) ; also on sheet 17 21 26 31
RST IN# MCH: R82.1 U5.AV20(RSTIN#)
SDVO_CTRL_CLK: U5.H35(SDVO_CTRL_CLK) ; also on sheet 35
SDVO_CTRL_DAT: U5.K36(SDVO_CTRL_DATA) ; also on sheet 35
SM_RCOMP_VOH: C66.1 C67.2 R63.2 R65.2 U5.BK31(SM_RCOMP_VOH)
SM_RCOMP_VOL: C68.1 C69.2 R65.1 R67.1 U5.BL31(SM_RCOMP_VOL)
SMDDR_VREF: C186.1 CN2.1(VREF) R68.2 ; also on sheet 33 38
SMDDR_VREF_MCH: R68.1 U5.AR49(SM_VREF_0) U5.AW4(SM_VREF_1)
SMDDR_VTERM: C206.1 C207.1 C208.1 C209.1 C210.1 C211.1 C212.1 C213.1 C217.1 C218.1 C219.1 C220.1 C221.1 C222.1 C223.1 C224.1 R120.2 R122.2 R124.2 RN1.2(R12) RN1.4(R22) RN1.6(R32) RN1.8(R42) RN3.2(R12) RN3.4(R22) RN3.6(R32) RN3.8(R42) RN5.2(R12) RN5.4(R22) RN5.6(R32) RN5.8(R42) RN7.2(R12) RN7.4(R22) RN7.6(R32) RN7.8(R42) RN9.2(R12) RN9.4(R22) RN9.6(R32) RN9.8(R42) RN11.2(R12) RN11.4(R22) RN11.6(R32) RN11.8(R42) ; also on sheet 32 33 37
VGA_BLU: R97.2 U5.H32(CRT_BLUE) ; also on sheet 26
VGA_GRN: R98.2 U5.K29(CRT_GREEN) ; also on sheet 26
VGA_RED: R99.2 U5.F29(CRT_RED) ; also on sheet 26
VTTLF1: C178.2 U5.A7(VTTLF1)
VTTLF2: C177.2 U5.F2(VTTLF2)
VTTLF3: C176.2 U5.AH1(VTTLF3)
N2322432: C131.1 U5.AW45(VCC_SM_LF1)
N2322745: C130.1 U5.BC39(VCC_SM_LF2)
N2323059: C129.2 U5.BE39(VCC_SM_LF3)
N2323374: C128.1 U5.BD17(VCC_SM_LF4)
N2323690: C127.1 U5.BD4(VCC_SM_LF5)
N2324007: C126.1 U5.AW8(VCC_SM_LF6)
N2324325: C125.1 U5.AT6(VCC_SM_LF7)
N37240377: CN2.198(SA0) R127.1
N37240379: CN2.200(SA1) R129.1
N48094341: C159.2 R111.2
N48388553: R87.1 U5.H39(L_BKLT_EN)
N48477695: R86.1 U5.R32(TEST_2)
N49157542: R93.2 U5.L41(LVDS_IBG)
N49239151: R83.2 U5.N20(THERMTRIP#)
N49615450: D1.3 R103.2
N49867053: D2.3 R116.2
N52104107: R94.2 U5.E27(TVA_DAC)
N52104236: R95.2 U5.G27(TVB_DAC)
N52104366: R96.2 U5.K27(TVC_DAC)
N52482300: R80.2 U5.L36(PM_EXT_TS#_0)
N55017452: C181.2 R112.1
N93471556: R81.2 U5.J36(PM_EXT_TS#_1)

Not connected (* = marked no-connect by the designer): CN2 69(NC4)* 83(NC1)* 84(A15)* 120(NC2)* 163(NCTEST)* 201(NC1GND)* 202(NC2GND)*; D1 2*; D2 2*; U5 A5(NC_11)* A35(RSVD41)* A39(GFX_VID_1)* A49(NC_15)* A50(NC_14)* AB50(PEG_RX_8)* AB51(PEG_RX#_8)* AC38(PEG_TX_9)* AC41(PEG_RX_11)* AC42(PEG_TX#_12)* AC45(PEG_RX_10)* AC46(PEG_TX#_10)* AC49(PEG_TX#_11)* AC50(PEG_TX_11)* AD39(PEG_TX#_9)* AD40(PEG_RX#_11)* AD43(PEG_TX_12)* AD44(PEG_RX#_10)* AD47(PEG_TX_10)* AE49(PEG_TX#_14)* AE50(PEG_TX_14)* AG39(PEG_TX_13)* AG41(PEG_RX#_15)* AG42(PEG_RX_15)* AG45(PEG_RX#_14)* AG46(PEG_RX#_12)* AG49(PEG_RX_13)* AH39(PEG_TX#_13)* AH43(PEG_TX_15)* AH44(PEG_TX#_15)* AH45(PEG_RX_14)* AH47(PEG_RX_12)* AH49(PEG_RX#_13)* AL36(RSVD12)* AM12(RSVD7)* AM36(RSVD11)* AM37(RSVD13)* AN13(RSVD8)* AR12(RSVD5)* AR13(RSVD6)* AR37(RSVD10)* AW20(RSVD35)* B34(RSVD44)* B36(RSVD43)* B37(RSVD42)* B39(GFX_VID_3)* B50(NC_13)* B51(RSVD21)* BC23(RSVD30)* BD24(RSVD31)* BF19(RSVD24)* BF23(RSVD28)* BG23(RSVD29)* BH20(RSVD25)* BH39(RSVD34)* BJ1(NC_9)* BJ18(RSVD27)* BJ20(RSVD22)* BJ51(NC_1)* BK1(NC_8)* BK2(NC_16)* BK18(RSVD26)* BK20(RSVD36)* BK22(RSVD23)* BK50(NC_3)* BK51(NC_2)* BL2(NC_7)* BL3(NC_6)* BL49(NC_5)* BL50(NC_4)* C34(RSVD45)* C38(GFX_VID_2)* C51(NC_12)* D20(RSVD14)* E1(NC_10)* E35(GFX_VID_0)* E36(GFX_VR_EN)* H10(RSVD20)* J12(RSVD9)* J50(PEG_RX_0)* J51(PEG_RX#_0)* L43(LVDS_VBG)* M35(TV_DCONSEL_0)* M47(PEG_RX_2)* N35(RSVD4)* N47(PEG_RX#_2)* P33(TV_DCONSEL_1)* P36(RSVD1)* P37(RSVD2)* R35(RSVD3)* R50(PEG_TX#_4)* R51(PEG_TX_4)* T41(PEG_RX_5)* T42(PEG_TX#_5)* T45(PEG_RX#_3)* T49(PEG_RX_4)* T50(PEG_RX#_4)* U40(PEG_RX#_5)* U43(PEG_TX_5)* U44(PEG_RX_3)* W38(PEG_TX#_8)* W41(PEG_RX_7)* W42(PEG_TX_6)* W45(PEG_RX_6)* W46(PEG_TX#_7)* W49(PEG_RX#_9)* Y39(PEG_TX_8)* Y40(PEG_RX#_7)* Y43(PEG_TX#_6)* Y44(PEG_RX#_6)* Y47(PEG_TX_7)* Y48(PEG_RX_9)*

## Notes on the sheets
sheet 9
- Change from 80.6 to 20 ref Intel 1.201
- < 0.1" . 15mils/15mils space
  use 1% R
- GMCH Strap pin
- Change to 4.02K 7/24
- 1.MCH_CFG_5 Low = DMI X2, High=DMIX4
- 2.MCH_CFG_9 PCI Exp Graphics Lane: Low =Reserved,High=Normal operation
- 3. CFG[13:12]  control the entry of the GMCH into different test modes
- 4.MCH_CFG_16 FSB Dynmic ODT: Low=Dynamic ODT Disabled,
                               High=Dynamic ODT Enabled.
- update per design guide v1.1
  8/31
- 5.MCH_CFG_18 VCC Select: LOW=1.05V, High=1.5V
- 6.MCH_CFG_19 DMI LANE Reversal: Low=Normal,High=LANES Reversed.
- 7.MCH_CFG_20 PCIE Backward interpoerability mode: Low= only
    SDVO or PCIE x1 is operational (defaults) ,High=SDVO and
    PCIE x1 are operation simultaneously via the PEG port.
- CFG[17:3] have internal pull-up
  CFG[19:18] have internal pull-down
sheet 10
- GMCH
- as close as to GMCH,
  20mils spacec from
  other signal
- signal CRTIREF spacing from other signal min 30mils
  R48 as close as GMCH
sheet 11
- 1400mA
- 3500mA
- 1000mA
sheet 12
- C141,C142,c197,c201,c177->E@0ohm
                          ->I@0.1uf/16v
- C176,c199->E@0ohm
           ->I@
- VTT
- 0.85A
- 350mA
- 0.1A
- 1.2A
- 100mA
- 0.25A
- 100mA
sheet 14
- DDR2 SO-DIMM SOCKET
- DDR2 TERMINATOR
- 1.27A
- TERMINATOR DECOUPLING CAPACITOR
